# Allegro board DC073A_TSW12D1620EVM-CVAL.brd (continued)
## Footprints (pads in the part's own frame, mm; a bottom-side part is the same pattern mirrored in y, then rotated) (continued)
CQFP_HFG_36_0P635MM
  rect 1.778x0.229 smd: 1(-6.985,2.54) 2(-6.985,1.905) 3(-6.985,1.27) 4(-6.985,0.635) 5(-6.985,0) 6(-6.985,-0.635) 7(-6.985,-1.27) 8(-6.985,-1.905) 9(-6.985,-2.54) 19(6.985,-2.54) 20(6.985,-1.905) 21(6.985,-1.27) 22(6.985,-0.635) 23(6.985,0) 24(6.985,0.635) 25(6.985,1.27) 26(6.985,1.905) 27(6.985,2.54)
  rect 0.229x1.778 smd: 10(-2.54,-6.985) 11(-1.905,-6.985) 12(-1.27,-6.985) 13(-0.635,-6.985) 14(0,-6.985) 15(0.635,-6.985) 16(1.27,-6.985) 17(1.905,-6.985) 18(2.54,-6.985) 28(2.54,6.985) 29(1.905,6.985) 30(1.27,6.985) 31(0.635,6.985) 32(0,6.985) 33(-0.635,6.985) 34(-1.27,6.985) 35(-1.905,6.985) 36(-2.54,6.985)
  rect 6.502x6.502 smd: 37(0,0)
DBV5
  rect 1.4x0.5 smd: 1(-1.1,0.95) 2(-1.1,0) 3(-1.1,-0.95) 4(1.1,-0.95) 5(1.1,0.95)
DIODE_MBRB2515L
  rect 3.048x1.016 smd: 1(5.652,-2.54) 3(5.652,2.54)
  round 0.013 smd: 2(5.652,0)
  rect 8.382x10.668 smd: 4(-5.652,0)
DIODE_SM_1N4148W
  rect 0.889x0.94 smd: 1(-1.575,0) 2(1.575,0)
DUAL_FLATPACK_TPS7H1101-SP
  rect 1.422x0.551 smd: 1(-7.303,4.445) 2(-7.303,3.175) 3(-7.303,1.905) 4(-7.303,0.635) 5(-7.303,-0.635) 6(-7.303,-1.905) 7(-7.303,-3.175) 8(-7.303,-4.445) 9(7.303,-4.445) 10(7.303,-3.175) 11(7.303,-1.905) 12(7.303,-0.635) 13(7.303,0.635) 14(7.303,1.905) 15(7.303,3.175) 16(7.303,4.445)
  rect 6.223x8.89 smd: 17(0,0)
HDR_THVT_1X2_100_M
  rect 1.473x1.473 hole 0.965: 1(0,0)
  round 1.473 hole 0.965: 2(0,-2.54)
HDR_THVT_1X3_100_M
  rect 1.575x1.575 hole 1.016: 1(0,0)
  round 1.575 hole 1.016: 2(0,-2.54) 3(0,-5.08)
HDR_THVT_1X4_100_M
  rect 1.473x1.473 hole 0.965: 1(0,0)
  round 1.473 hole 0.965: 2(0,-2.54) 3(0,-5.08) 4(0,-7.62)
IND_0402
  rect 0.406x0.66 smd: 1(-0.432,0) 2(0.432,0)
IND_0603
  rect 0.635x1.016 smd: 1(-0.635,0) 2(0.635,0)
IND_SM_6P7MMX6P7MM
  rect 2.5x2.4 smd: 1(-3.1,0) 2(3.1,0)
LCCC_14_5P5X6MM_1P27
  custom 0.159x0.159 smd: 1(-2.642,1.27) 3(-2.642,-1.27) 4(-1.905,-2.413) 7(1.905,-2.413) 8(2.642,-1.27) 10(2.642,1.27) 11(1.905,2.388) 14(-1.905,2.388)
  rect 1.524x0.635 smd: 2(-2.642,0) 9(2.642,0)
  rect 0.635x1.524 smd: 5(-0.635,-2.413) 6(0.635,-2.413) 12(0.635,2.388) 13(-0.635,2.388)
  rect 2.997x2.489 smd: 15(0,0)
LED_0805
  rect 1.422x1.524 smd: 1(-1.143,0) 2(1.143,0)
LMT01-SP
  rect 0.533x4.445 smd: 1(-0.635,0) 2(0.635,0)
LQFP_64_402X402_20
  round 1.016 smd: (-6.35,6.35) (6.35,-6.35)
  rect 2.032x0.33 smd: 1(-5.625,3.75) 2(-5.625,3.25) 3(-5.625,2.75) 4(-5.625,2.25) 5(-5.625,1.75) 6(-5.625,1.25) 7(-5.625,0.75) 8(-5.625,0.25) 9(-5.625,-0.25) 10(-5.625,-0.75) 11(-5.625,-1.25) 12(-5.625,-1.75) 13(-5.625,-2.25) 14(-5.625,-2.75) 15(-5.625,-3.25) 16(-5.625,-3.75) 33(5.625,-3.75) 34(5.625,-3.25) 35(5.625,-2.75) 36(5.625,-2.25) 37(5.625,-1.75) 38(5.625,-1.25) 39(5.625,-0.75) 40(5.625,-0.25) 41(5.625,0.25) 42(5.625,0.75) 43(5.625,1.25) 44(5.625,1.75) 45(5.625,2.25) 46(5.625,2.75) 47(5.625,3.25) 48(5.625,3.75)
  rect 0.33x2.032 smd: 17(-3.75,-5.625) 18(-3.25,-5.625) 19(-2.75,-5.625) 20(-2.25,-5.625) 21(-1.75,-5.625) 22(-1.25,-5.625) 23(-0.75,-5.625) 24(-0.25,-5.625) 25(0.25,-5.625) 26(0.75,-5.625) 27(1.25,-5.625) 28(1.75,-5.625) 29(2.25,-5.625) 30(2.75,-5.625) 31(3.25,-5.625) 32(3.75,-5.625) 49(3.75,5.625) 50(3.25,5.625) 51(2.75,5.625) 52(2.25,5.625) 53(1.75,5.625) 54(1.25,5.625) 55(0.75,5.625) 56(0.25,5.625) 57(-0.25,5.625) 58(-0.75,5.625) 59(-1.25,5.625) 60(-1.75,5.625) 61(-2.25,5.625) 62(-2.75,5.625) 63(-3.25,5.625) 64(-3.75,5.625)
MFG125_PLATED
  round 3.556 hole 3.175: 1(0,0)
MSOP_8_118X118_0P65MM
  rect 1.45x0.46 smd: 1(-2.2,0.975) 2(-2.2,0.325) 3(-2.2,-0.325) 4(-2.2,-0.975) 5(2.2,-0.975) 6(2.2,-0.325) 7(2.2,0.325) 8(2.2,0.975)
OSC_6_SM_SIA0006B
  rect 0.914x0.635 smd: 1(-1.05,1.27) 2(-1.05,0) 3(-1.05,-1.27) 4(1.05,-1.27) 5(1.05,0) 6(1.05,1.27)
PROBE_POINT_30PAD
  round 0.762 smd: 1(0,0)
QFN_48_281X281_0P50MM_RGZ
  oval 0.838x0.279 smd: 1(-3.525,2.75) 2(-3.525,2.25) 3(-3.525,1.75) 4(-3.525,1.25) 5(-3.525,0.75) 6(-3.525,0.25) 7(-3.525,-0.25) 8(-3.525,-0.75) 9(-3.525,-1.25) 10(-3.525,-1.75) 11(-3.525,-2.25) 12(-3.525,-2.75) 25(3.525,-2.75) 26(3.525,-2.25) 27(3.525,-1.75) 28(3.525,-1.25) 29(3.525,-0.75) 30(3.525,-0.25) 31(3.525,0.25) 32(3.525,0.75) 33(3.525,1.25) 34(3.525,1.75) 35(3.525,2.25) 36(3.525,2.75)
  oval 0.279x0.838 smd: 13(-2.75,-3.525) 14(-2.25,-3.525) 15(-1.75,-3.525) 16(-1.25,-3.525) 17(-0.75,-3.525) 18(-0.25,-3.525) 19(0.25,-3.525) 20(0.75,-3.525) 21(1.25,-3.525) 22(1.75,-3.525) 23(2.25,-3.525) 24(2.75,-3.525) 37(2.75,3.525) 38(2.25,3.525) 39(1.75,3.525) 40(1.25,3.525) 41(0.75,3.525) 42(0.25,3.525) 43(-0.25,3.525) 44(-0.75,3.525) 45(-1.25,3.525) 46(-1.75,3.525) 47(-2.25,3.525) 48(-2.75,3.525)
  rect 5.6x5.6 smd: 49(0,0)
SMA_THVT_SMT_250X250
  round 0.787 smd: 1(0,0)
  round 1.829 hole 1.499: 2(-2.54,-2.54) 3(2.54,-2.54) 4(2.54,2.54) 5(-2.54,2.54)
SO_8_207X207_50
  rect 1.702x0.66 smd: 1(-3.645,1.905) 2(-3.645,0.635) 3(-3.645,-0.635) 4(-3.645,-1.905) 5(3.645,-1.905) 6(3.645,-0.635) 7(3.645,0.635) 8(3.645,1.905)
SOIC_8_197X157_50
  rect 2.159x0.61 smd: 1(-2.44,1.905) 2(-2.44,0.635) 3(-2.44,-0.635) 4(-2.44,-1.905) 5(2.44,-1.905) 6(2.44,-0.635) 7(2.44,0.635) 8(2.44,1.905)
SON_Q5B_8
  rect 1.372x0.711 smd: 1(-2.767,1.905) 2(-2.767,0.635) 3(-2.767,-0.635) 4(-2.767,-1.905) 5(2.767,-1.905) 6(2.767,-0.635) 7(2.767,0.635) 8(2.767,1.905)
SOT_5_120X69_37
  rect 0.61x1.524 smd: 1(-0.95,-1.75) 2(0,-1.75) 3(0.95,-1.75) 4(0.95,1.75) 5(-0.95,1.75)
SOT_5_120X69_57
  rect 0.61x1.524 smd: 1(-0.95,-1.75) 2(0,-1.75) 3(0.95,-1.75) 4(0.95,1.75) 5(-0.95,1.75)
SW_SMVT_SPST_ES02
  rect 0.889x2.159 smd: 1(-2.54,-4.445) 2(0,-4.445) 3(2.54,-4.445)
  rect 2.413x1.524 smd: 4(-5.385,4.445) 5(5.385,4.445)
SW_THVT_SPST_PTS635SL43
  round 2.159 hole 1.397: 1(-3.251,0) 2(3.251,0)
TANT_B
  rect 2.032x2.286 smd: 1(-1.524,0) 2(1.524,0)
TANT_D
  rect 2.108x2.591 smd: 1(-2.896,0) 2(2.896,0)
TANT_X
  rect 2.108x2.591 smd: 1(-2.896,0) 2(2.896,0)
TFMR_5_150X150_50
  rect 1.651x0.762 smd: 1(1.587,1.27) 2(1.587,0) 3(1.587,-1.27) 4(-1.587,-1.27) 6(-1.587,1.27)
TP_THVT_100_RND
  round 2.54 hole 1.016: 1(0,0)
TP_THVT_125_RND_063D
  round 2.362 hole 1.6: 1(0,0)
TSSOP_16_201X177_26
  rect 1.778x0.406 smd: 1(-2.825,2.275) 2(-2.825,1.625) 3(-2.825,0.975) 4(-2.825,0.325) 5(-2.825,-0.325) 6(-2.825,-0.975) 7(-2.825,-1.625) 8(-2.825,-2.275) 9(2.825,-2.275) 10(2.825,-1.625) 11(2.825,-0.975) 12(2.825,-0.325) 13(2.825,0.325) 14(2.825,0.975) 15(2.825,1.625) 16(2.825,2.275)
unnamed#2
  round 1.016 smd: 1(0,0)
XTAL_2_SM_126X197
  rect 1.9x2.4 smd: 1(-2.05,0) 2(2.05,0)
XTAL_2_SM_MS3V-T1R_264X55
  rect 2.413x1.524 smd: (-3.1,0)
  rect 1.118x0.61 smd: 1(2.45,-0.45) 2(2.45,0.45)
XTAL_HC-49UX
  round 1.524 hole 0.914: 1(0,0) 2(5.08,0)

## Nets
1V9A: C78.1 C79.1 C80.1 C81.1 C82.1 C83.1 C84.1 C85.1 C86.1 C87.1 C88.1 C89.1 C90.1 C91.1 C92.1 C93.1 C94.1 C95.1 C96.1 R85.2 U4.A2(VA#A2) U4.A6(VA#A6) U4.B6(VA#B6) U4.C7(VA#C7) U4.D1(VA#D1) U4.D8(VA#D8) U4.D9(VA#D9) U4.E1(VA#E1) U4.F1(VA#F1) U4.H4(VA#H4) U4.N4(VA#N4) U4.R1(VA#R1) U4.T1(VA#T1) U4.U8(VA#U8) U4.U9(VA#U9) U4.W6(VA#W6) U4.Y2(VA#Y2) U4.Y6(VA#Y6)
1V9DR: C97.1 C98.1 C99.1 C100.1 C101.1 C102.1 C103.1 C104.1 C105.1 C106.1 C107.1 C108.1 C109.1 C110.1 C111.1 C112.1 C113.1 R87.2 U4.A11(VDR#A11) U4.A15(VDR#A15) U4.C18(VDR#C18) U4.D11(VDR#D11) U4.D15(VDR#D15) U4.D17(VDR#D17) U4.J17(VDR#J17) U4.J20(VDR#J20) U4.R17(VDR#R17) U4.R20(VDR#R20) U4.T17(VDR#T17) U4.U11(VDR#U11) U4.U15(VDR#U15) U4.U16(VDR#U16) U4.Y11(VDR#Y11) U4.Y15(VDR#Y15)
1V9E: C117.1 C118.1 C119.1 C120.1 C121.1 C122.1 C123.1 R86.2 U4.A8(VE#A8) U4.B9(VE#B9) U4.C8(VE#C8) U4.V8(VE#V8) U4.W9(VE#W9) U4.Y8(VE#Y8)
1V9TC: C63.1 C64.1 C65.1 C66.1 C67.1 C68.1 C69.1 C70.1 C71.1 C72.1 C73.1 C74.1 C75.1 C76.1 C77.1 R88.2 U4.G1(VTC#G1) U4.G3(VTC#G3) U4.G4(VTC#G4) U4.H2(VTC#H2) U4.J3(VTC#J3) U4.K3(VTC#K3) U4.L3(VTC#L3) U4.M3(VTC#M3) U4.N2(VTC#N2) U4.P1(VTC#P1) U4.P3(VTC#P3) U4.P4(VTC#P4) U4.R3(VTC#R3) U4.R4(VTC#R4)
3.3VLMX: C215.1 C216.1 C217.1 FB7.1 FB8.1 FB9.1 R180.1 U18.6(OUT1) U18.7(OUT2) U18.8(OUT3)
4.8VLMH: C226.1 C227.1 C228.1 FB10.1 R182.1 U19.6(OUT1) U19.7(OUT2) U19.8(OUT3)
5.0V_IN: J33.1 SW3.1
5VIN: C180.1 C181.1 C182.1 C183.1 C206.1 C207.1 C213.1 C214.1 C224.1 C225.1 F1.2 Q1.1(S1) Q1.2(S2) Q1.3(S3) R160.1 R161.1 R162.1 R178.1 U15.5(VIN) U15.6(PVIN#6) U15.7(PVIN#7) U17.15(VIN) U18.1(\\S\H\D\N\) U18.2(IN1) U18.3(IN2) U18.4(IN3) U19.1(\\S\H\D\N\) U19.2(IN1) U19.3(IN2) U19.4(IN3)
+2.2V: C185.1 C186.1 C187.1 C188.1 C194.1 C195.1 C196.1 L11.2 PP10.1 R163.2 R168.1 R170.1
+2.5V: C44.1 C45.1 C46.2 C47.2 C48.2 C49.2 C50.2 C51.2 C52.2 C55.2 C56.2 C208.1 C209.1 FB6.2 JP10.1(PIN1) PP18.1 U6.1(VCC#1) U6.9(VCC#9) U6.10(VCC#10) U6.17(VCC#17) U6.18(VCC#18) U6.27(VCC#27) U6.28(VCC#28) U6.35(VCC#35) U6.36(VCC#36)
+3.3V_LMX: C127.1 C129.2 C133.2 C218.1 C219.1 C220.1 C221.1 FB8.2 PP15.1 R98.1 R101.1 R103.1 R106.1 R108.1 R109.1 R110.1 Y1.6(VDD)
+3.3V_LMXRF: C222.1 C223.1 FB9.2 L9.2 L10.2 PP16.1
+4.8V_LMH: C9.1 C10.1 C11.1 C12.1 C25.1 C26.1 C27.1 C28.1 C229.1 C230.1 FB10.2 JP1.1 JP2.1 PP17.1 R14.1 U1.1(VS+#1) U1.10(VS+#10) U2.1(VS+#1) U2.10(VS+#10)
GND: C4.2 C7.1 C9.2 C10.2 C11.2 C12.2 C15.2 C19.2 C21.1 C25.2 C26.2 C27.2 C28.2 C30.2 C31.2 C34.2 C35.2 C36.2 C38.1 C39.1 C44.2 C45.2 C46.1 C47.1 C48.1 C49.1 C50.1 C51.1 C52.1 C55.1 C56.1 C63.2 C64.2 C65.2 C66.2 C67.2 C68.2 C69.2 C70.2 C71.2 C72.2 C73.2 C74.2 C75.2 C76.2 C77.2 C78.2 C79.2 C80.2 C81.2 C82.2 C83.2 C84.2 C85.2 C86.2 C87.2 C88.2 C89.2 C90.2 C91.2 C92.2 C93.2 C94.2 C95.2 C96.2 C97.2 C98.2 C99.2 C100.2 C101.2 C102.2 C103.2 C104.2 C105.2 C106.2 C107.2 C108.2 C109.2 C110.2 C111.2 C112.2 C113.2 C114.2 C115.2 C116.2 C117.2 C118.2 C119.2 C120.2 C121.2 C122.2 C123.2 C124.2 C125.2 C126.2 C127.2 C129.1 C130.2 C132.2 C133.1 C134.2 C137.2 C139.2 C141.2 C142.2 C143.2 C145.2 C146.2 C147.1 C148.1 C149.2 C150.2 C151.1 C152.1 C153.1 C154.1 C155.1 C156.2 C157.2 C158.2 C159.2 C160.2 C161.2 C162.2 C163.2 C164.2 C165.2 C166.2 C167.2 C168.2 C169.2 C170.2 C171.2 C172.2 C173.2 C174.2 C175.2 C176.2 C177.2 C178.2 C179.2 C180.2 C181.2 C182.2 C183.2 C184.2 C185.2 C186.2 C187.2 C189.2 C190.2 C191.2 C192.2 C193.2 C194.2 C195.2 C196.2 C198.2 C199.2 C200.2 C201.2 C202.2 C203.2 C204.2 C205.2 C206.2 C207.2 C208.2 C209.2 C210.2 C211.2 C212.2 C213.2 C214.2 C216.2 C217.2 C218.2 C219.2 C220.2 C221.2 C222.2 C223.2 C224.2 C225.2 C227.2 C228.2 C229.2 C230.2 C236.2 C237.2 C238.2 D6.2(CATHODE) D8.2(CATHODE) D9.1 D9.3 D10.2(CATHODE) FB4.2 FB5.2 J1.2(SHIELD1) J1.3(SHIELD2) J1.4(SHIELD3) J1.5(SHIELD4) J2.2(SHIELD1) J2.3(SHIELD2) J2.4(SHIELD3) J2.5(SHIELD4) J3.2(SHIELD1) J3.3(SHIELD2) J3.4(SHIELD3) J3.5(SHIELD4) J4.2(SHIELD1) J4.3(SHIELD2) J4.4(SHIELD3) J4.5(SHIELD4) J5.2(SHIELD1) J5.3(SHIELD2) J5.4(SHIELD3) J5.5(SHIELD4) J6.2(SHIELD1) J6.3(SHIELD2) J6.4(SHIELD3) J6.5(SHIELD4) J10.1 J13.2(SHIELD1) J13.3(SHIELD2) J13.4(SHIELD3) J13.5(SHIELD4) J14.2(SHIELD1) J14.3(SHIELD2) J14.4(SHIELD3) J14.5(SHIELD4) J15.2(SHIELD1) J15.3(SHIELD2) J15.4(SHIELD3) J15.5(SHIELD4) J16.2(SHIELD1) J16.3(SHIELD2) J16.4(SHIELD3) J16.5(SHIELD4) J17.2(SHIELD1) J17.3(SHIELD2) J17.4(SHIELD3) J17.5(SHIELD4) J18.2(SHIELD1) J18.3(SHIELD2) J18.4(SHIELD3) J18.5(SHIELD4) J19.2(SHIELD1) J19.3(SHIELD2) J19.4(SHIELD3) J19.5(SHIELD4) J20.2(SHIELD1) J20.3(SHIELD2) J20.4(SHIELD3) J20.5(SHIELD4) J21.2(SHIELD1) J21.3(SHIELD2) J21.4(SHIELD3) J21.5(SHIELD4) J22.2(SHIELD1) J22.3(SHIELD2) J22.4(SHIELD3) J22.5(SHIELD4) J24.2 J26.2(SHIELD1) J26.3(SHIELD2) J26.4(SHIELD3) J26.5(SHIELD4) J27.2(SHIELD1) J27.3(SHIELD2) J27.4(SHIELD3) J27.5(SHIELD4) J28.A1 J28.A4 J28.A5 J28.A8 J28.A9 J28.A12 J28.A13 J28.A16 J28.A17 J28.A20 J28.A21 J28.A24 J28.A25 J28.A28 J28.A29 J28.A32 J28.A33 J28.A36 J28.A37 J28.A40 J28.B2 J28.B3 J28.B6 J28.B7 J28.B10 J28.B11 J28.B14 J28.B15 J28.B18 J28.B19 J28.B22 J28.B23 J28.B26 J28.B27 J28.B30 J28.B31 J28.B34 J28.B35 J28.B38 J28.B39 J28.C1 J28.C4 J28.C5 J28.C8 J28.C9 J28.C12 J28.C13 J28.C16 J28.C17 J28.C21 J28.C24 J28.C25 J28.C28 J28.C29 J28.C32 J28.C33 J28.C36 J28.C38 J28.C40 J28.D2 J28.D3 J28.D6 J28.D7 J28.D10 J28.D13 J28.D16 J28.D22 J28.D25 J28.D28 J28.D37 J28.D39 J28.E1 J28.E4 J28.E5 J28.E11 J28.E17 J28.E20 J28.E23 J28.E26 J28.E29 J28.E32 J28.E35 J28.E38 J28.E40 J28.F2 J28.F3 J28.F9 J28.F12 J28.F15 J28.F18 J28.F21 J28.F24 J28.F27 J28.F30 J28.F33 J28.F36 J28.F39 J28.G1 J28.G4 J28.G5 J28.G8 J28.G11 J28.G14 J28.G20 J28.G23 J28.G26 J28.G29 J28.G32 J28.G35 J28.G38 J28.G40 J28.H3 J28.H9 J28.H12 J28.H21 J28.H24 J28.H27 J28.H30 J28.H33 J28.H36 J28.H39 J28.J1 J28.J5 J28.J8 J28.J11 J28.J14 J28.J20 J28.J26 J28.J29 J28.J32 J28.J35 J28.J38 J28.J40 J28.K3 J28.K6 J28.K9 J28.K15 J28.K18 J28.K21 J28.K24 J28.K27 J28.K30 J28.K33 J28.K36 J28.K39 J30.3 J32.5(GND) J32.6(GND1) J32.7(GND2) J32.8(GND3) J32.9(GND4) J33.2 J33.3 J34.2 J36.9 JP3.3(PIN3) JP4.3(PIN3) JP5.3(PIN3) JP6.3(PIN3) JP7.3(PIN3) JP8.3(PIN3) JP9.3(PIN3) MT1.1 MT2.1 MT3.1 MT4.1 R5.2 R8.2 R10.2 R13.2 R15.2 R20.2 R21.2 R26.2 R28.2 R32.2 R33.2 R34.2 R37.2 R38.2 R51.2 R61.2 R62.2 R67.2 R68.2 R71.2 R72.2 R77.2 R78.2 R84.2 R91.2 R92.1 R94.1 R95.2 R96.2 R102.2 R111.2 R113.2 R118.2 R127.2 R140.1 R164.1 R165.1 R167.2 R175.2 R176.2 R179.2 R181.2 R183.2 R186.1 R189.2 SW1.1 SW2.1 T1.4(PRIMARY) TP11.1(TP) TP12.1(TP) TP13.1(TP) TP14.1(TP) TP15.1(TP) U1.3(VS-#3) U1.8(VS-#8) U1.11(GND#11) U1.14(GND#14) U1.15(PWRPAD) U2.3(VS-#3) U2.8(VS-#8) U2.11(GND#11) U2.14(GND#14) U2.15(PWRPAD) U3.4(V-) U4.A1(GND#A1) U4.A7(GND#A7) U4.A9(GNDE#A9) U4.A13(GNDDR#A13) U4.A17(GNDDR#A17) U4.A20(GNDDR#A20) U4.AA2(GND#AA2) U4.AA3(GND#AA3) U4.AA4(GND#AA4) U4.AA5(GND#AA5) U4.AA6(GND#AA6) U4.AA7(GND#AA7) U4.AA8(GND#AA8) U4.AA9(GND#AA9) U4.AA10(GND#AA10) U4.AA11(GND#AA11) U4.AB1(GND#AB1) U4.AB2(GND#AB2) U4.AB3(GND#AB3) U4.AB4(GND#AB4) U4.AB5(GND#AB5) U4.AB6(GND#AB6) U4.AB7(GND#AB7) U4.AB8(GND#AB8) U4.AB9(GND#AB9) U4.AB10(GND#AB10) U4.AB11(GND#AB11) U4.AC1(GND#AC1) U4.AC2(GND#AC2) U4.AC3(GND#AC3) U4.AC4(GND#AC4) U4.AC5(GND#AC5) U4.AC6(GND#AC6) U4.AC7(GND#AC7) U4.AC8(GND#AC8) U4.AC9(GND#AC9) U4.AC10(GND#AC10) U4.AC11(GND#AC11) U4.AD1(GND#AD1) U4.AD2(GND#AD2) U4.AD3(GND#AD3) U4.AD4(GND#AD4) U4.AD5(GND#AD5) U4.AD6(GND#AD6) U4.AD7(GND#AD7) U4.AD8(GND#AD8) U4.AD9(GND#AD9) U4.AD10(GND#AD10) U4.AD11(GND#AD11) U4.AE1(GND#AE1) U4.AE2(GND#AE2) U4.AE3(GND#AE3) U4.AE4(GND#AE4) U4.AE5(GND#AE5) U4.AE6(GND#AE6) U4.AE7(GND#AE7) U4.AE8(GND#AE8) U4.AE9(GND#AE9) U4.AE10(GND#AE10) U4.AE11(GND#AE11) U4.AF1(GND#AF1) U4.AF2(GND#AF2) U4.AF3(GND#AF3) U4.AF4(GND#AF4) U4.AF5(GND#AF5) U4.AF6(GND#AF6) U4.AF7(GND#AF7) U4.AF8(GND#AF8) U4.AF9(GND#AF9) U4.AF10(GND#AF10) U4.AF11(GND#AF11) U4.AG1(GND#AG1) U4.AG2(GND#AG2) U4.AG3(GND#AG3) U4.AG4(GND#AG4) U4.AG5(GND#AG5) U4.AG6(GND#AG6) U4.AG7(GND#AG7) U4.AG8(GND#AG8) U4.AG9(GND#AG9) U4.AG10(GND#AG10) U4.AG11(GND#AG11) U4.AH1(GND#AH1) U4.AH2(GND#AH2) U4.AH3(GND#AH3) U4.AH4(GND#AH4) U4.AH5(GND#AH5) U4.AH6(GND#AH6) U4.AH7(GND#AH7) U4.AH8(GND#AH8) U4.AH9(GND#AH9) U4.AH10(GND#AH10) U4.AH11(GND#AH11) U4.AJ1(GND#AJ1) U4.AJ2(GND#AJ2) U4.AJ3(GND#AJ3) U4.AJ4(GND#AJ4) U4.AJ5(GND#AJ5) U4.AJ6(GND#AJ6) U4.AJ7(GND#AJ7) U4.AJ8(GND#AJ8) U4.AJ9(GND#AJ9) U4.AJ10(GND#AJ10) U4.AJ11(GND#AJ11) U4.AK1(GND#AK1) U4.AK2(GND#AK2) U4.AK3(GND#AK3) U4.AK4(GND#AK4) U4.AK5(GND#AK5) U4.AK6(GND#AK6) U4.AK7(GND#AK7) U4.AK8(GND#AK8) U4.AK9(GND#AK9) U4.AK10(GND#AK10) U4.AK11(GND#AK11) U4.AL1(GND#AL1) U4.AL2(GND#AL2) U4.AL3(GND#AL3) U4.AL4(GND#AL4) U4.AL5(GND#AL5) U4.AL6(GND#AL6) U4.AL7(GND#AL7) U4.AL8(GND#AL8) U4.AL9(GND#AL9) U4.AL10(GND#AL10) U4.AL11(GND#AL11) U4.B2(GND#B2) U4.B7(GND#B7) U4.B8(GNDE#B8) U4.C6(GND#C6) U4.C9(GNDE#C9) U4.D4(GND#D4) U4.D5(GND#D5) U4.D13(GNDDR#D13) U4.D16(GNDDR#D16) U4.E4(GND#E4) U4.E17(GNDDR#E17) U4.F2(GNDTC#F2) U4.F17(GNDDR#F17) U4.F20(GNDDR#F20) U4.G2(GNDTC#G2) U4.H3(GNDTC#H3) U4.J2(GNDTC#J2) U4.K1(GND#K1) U4.K4(GNDTC#K4) U4.L1(GND#L1) U4.L4(GNDTC#L4) U4.M2(GNDTC#M2) U4.M17(GNDDR#M17) U4.M20(GNDDR#M20) U4.N3(GNDTC#N3) U4.P2(GNDTC#P2) U4.R2(GNDTC#R2) U4.T2(GNDTC#T2) U4.T3(GNDTC#T3) U4.T4(GND#T4) U4.U1(GNDTC#U1) U4.U4(GND#U4) U4.U5(GND#U5) U4.U13(GNDDR#U13) U4.U17(GNDDR#U17) U4.V9(GNDE#V9) U4.V18(GNDDR#V18) U4.W2(GND#W2) U4.W7(GND#W7) U4.W8(GNDE#W8) U4.Y1(GND#Y1) U4.Y7(GND#Y7) U4.Y9(GNDE#Y9) U4.Y13(GNDDR#Y13) U4.Y17(GNDDR#Y17) U4.Y20(GNDDR#Y20) U5.5(A0) U5.6(GND) U5.11(PAD) U6.37(THERMPAD) U7.3(FS0) U7.4(FS1) U7.6(GND#6) U7.8(GND#8) U7.10(GND#10) U7.15(FS2) U7.16(FS3) U7.17(FS4) U7.18(FS5) U7.19(FS6) U7.20(FS7) U7.23(GND#23) U7.24(GND#24) U7.28(GND#28) U7.31(GND#31) U7.35(GND#35) U7.38(GND#38) U7.40(GND#40) U7.43(SYSREFREG) U7.51(GND#51) U7.54(GND#54) U7.60(GND#60) U7.61(GND#61) U7.65(PWRPAD) U8.3(A2) U8.4(VSS) U9.7(DIR3) U9.10(GND) U10.2(GND) U11.3(GND) U12.1(GND#1) U12.5(GND#5) U12.10(AGND) U12.11(GND#11) U12.13(TEST) U12.15(GND#15) U12.25(GND#25) U12.35(GND#35) U12.47(GND#47) U12.51(GND#51) U13.5(VSS) U14.2(GND) U15.1(GND) U15.8(PGND#8) U15.9(PGND#9) U15.10(PGND#10) U15.21(PWRPAD) U16.8(GND) U16.17(PWRPAD) U17.1(GND#1) U17.8(GND#8) U17.9(GND#9) U17.11(COMP IN) U17.16(GND#16) U18.10(GND) U18.11(PWRPAD) U19.10(GND) U19.11(PWRPAD) U20.36(DVSS) U20.49(THERMPAD) Y1.3(GND)
VBUS: C167.1 R132.1 U10.1(IN) U10.3(EN)
VBUSS: C163.1 FB3.1 U10.5(OUT)
VDDD33: C30.1 C31.1 C34.1 C35.1 C36.1 C156.1 C166.1 C170.1 C176.1 C177.1 C178.1 C179.1 C211.1 C212.1 C236.1 C237.1 D5.1(ANODE) D7.1(ANODE) FB1.1 FB2.1 FB7.2 J36.4 JP11.1(PIN1) JP12.3(PIN3) JP13.3(PIN3) PP14.1 R39.1 R41.1 R47.1 R48.1 R141.1 R142.1 R145.1 R146.1 R147.1 R148.1 R187.1 R190.1 U3.8(V+) U5.1(V+) U5.10(A1) U9.1(DIR1) U9.2(DIR2) U9.8(DIR4) U9.16(VCCA) U11.5(VCC) U12.20(VCCIO#20) U12.31(VCCIO#31) U12.42(VCCIO#42) U12.56(VCCIO#56) U13.8(VCC) U20.37(DVCC)
VDDL19: C157.1 C192.1 C193.1 FB4.3 J12.1 JP3.1(PIN1) JP4.1(PIN1) JP5.1(PIN1) JP6.1(PIN1) JP7.1(PIN1) JP8.1(PIN1) JP9.1(PIN1) PP12.1 R29.1 R30.1 R35.1 R119.1 U9.15(VCCB)
VEE: JP10.3(PIN3) R84.1 U6.8(VEE)
VINI+: C2.2 R1.2 U4.H1(VINI+)
VINI-: C14.2 R12.2 U4.J1(VINI-)
VINQ+: C24.2 R27.2 U4.N1(VINQ+)
VINQ-: C17.2 R16.2 U4.M1(VINQ-)
1P8V_USB: C168.1 C169.1 C171.1 C172.1 C173.1 PP9.1 U12.12(VCORE#12) U12.37(VCORE#37) U12.49(VREGOUT) U12.64(VCORE#64)
2: D9.2
3P3USB: C160.1 C161.1 FB2.2 PP6.1 U12.9(VPLL)
3P3V_RX: PP3.1 R115.2
3P3VAUX: C155.2 J28.D32 J30.4 U8.8(VCC)
12P0V_RX: J28.C35 J28.C37
/CS: R191.2 U20.39(P2.3/TA0.0)
/RST: C238.1 J36.11 R190.2 SW2.2 U20.23(R\S\T\/NMI/SBWTDIO)
ADC_CLK: PP7.1 R122.2 U4.C5(SCLK)
ADC_SCSB: PP8.1 R125.2 U4.C4(\\S\C\S\)
ADC_SDI: PP4.1 R123.2 U4.B4(SDI)
ADC_SDO: PP5.1 R124.2 U4.A3(SDO)
AIN: C1.2 R3.1
AINI: C1.1 J2.1(CENTER) R5.1
AINQ: C29.1 J5.1(CENTER) R26.1
AIP: C6.2 R7.1
AQN: C16.2 R18.1
AQP: C29.2 R25.1
BDBUS0: R134.1 U12.26(BDBUS0)
BDBUS1: U11.2(A) U12.27(BDBUS1)
BDBUS2: R136.1 U12.28(BDBUS2)
BDBUS3: U11.1(O\E\) U12.29(BDBUS3)
CALRUN: R40.1 TP1.1(TP) U4.B5(CALRUN)
CALRUN_FMC: J28.G18 R40.2
CALTRG: J9.2 R38.1 U4.D6(CAL)
CDBUS0: R138.1 U12.38(CDBUS0)
CDBUS1: R143.1 U12.39(CDBUS1)
CDBUS2: R142.2 R149.1 U12.40(CDBUS2)
CDBUS3: R141.2 R150.1 U12.41(CDBUS3)
CDBUS4: R151.1 U12.43(CDBUS4)
CLK+: C40.1 R53.2 T1.3(SECONDARY)
CLK-: C43.1 R53.1 T1.1(SECONDARY_DOT)
CLKN: C42.2 C43.2 U4.V1(CLK-)
CLKP: C40.2 C41.2 U4.U2(CLK+)
CPOUT: C131.1 C132.1 R90.1 U7.22(CPOUT)
DCLK_DI+: C59.2 J28.D20 R195.2
DCLK_DI-: C60.2 J28.D21 R194.2
DCLK_DID+: C57.2 J28.G6
DCLK_DID-: C58.2 J28.G7
DCLK_DQ+: C61.2 J28.K25 R197.1
DCLK_DQ-: C62.2 J28.K26 R196.1
DCLK_DQD+: C53.2 J28.F4
DCLK_DQD-: C54.2 J28.F5
DCLK_RST+: J13.1(CENTER) U4.V2(DCLK_RST+)
DCLK_RST-: J16.1(CENTER) U4.W1(DCLK_RST-)
DCLKI+: R64.2 R73.2 U4.K19(DCLKI+)
DCLKI-: R65.2 R75.2 U4.K20(DCLKI-)
DCLKIN: R65.1 R194.1
DCLKIP: R64.1 R195.1
DCLKQ+: R80.2 R82.2 U4.L19(DCLKQ+)
DCLKQ-: R81.2 R83.2 U4.L20(DCLKQ-)
DCLKQN: R81.1 R196.2
DCLKQP: R80.1 R197.2
DDRPH: JP9.2(PIN2) U4.W4(DDRPH)
DES: JP7.2(PIN2) U4.V5(DES)
DEVCLKIN: J21.1(CENTER) T1.6(PRIMARY_DOT)
DI0+: J28.C22 U4.B18(DI0)
DI0-: J28.C23 U4.C17(DI0-)
DI1+: J28.H22 U4.B19(DI1+)
DI1-: J28.H23 U4.B20(DI1-)
DI2+: J28.G21 U4.C19(DI2+)
DI2-: J28.G22 U4.C20(DI2-)
DI3+: J28.H25 U4.D18(DI3+)
DI3-: J28.H26 U4.E18(DI3-)
DI4+: J28.G24 U4.D19(DI4+)
DI4-: J28.G25 U4.D20(DI4-)
DI5+: J28.D23 U4.E19(DI5+)
DI5-: J28.D24 U4.E20(DI5-)
DI6+: J28.H28 U4.F18(DI6+)
DI6-: J28.H29 U4.F19(DI6-)
DI7+: J28.G27 U4.G17(DI7+)
DI7-: J28.G28 U4.G18(DI7-)
DI8+: J28.D26 U4.G19(DI8+)
DI8-: J28.D27 U4.G20(DI8-)
DI9+: J28.C26 U4.H17(DI9+)
DI9-: J28.C27 U4.H18(DI9-)
DI10+: J28.H31 U4.H19(DI10+)
DI10-: J28.H32 U4.H20(DI10-)
DI11+: J28.G30 U4.J18(DI11+)
DI11-: J28.G31 U4.J19(DI11-)
DID0+: J28.D8 U4.A10(DID0+)
DID0-: J28.D9 U4.B10(DID0-)
DID1+: J28.H7 U4.C10(DID1+)
DID1-: J28.H8 U4.D10(DID1-)
DID2+: J28.G9 U4.B11(DID2+)
DID2-: J28.G10 U4.C11(DID2-)
DID3+: J28.H10 U4.A12(DID3+)
DID3-: J28.H11 U4.B12(DID3-)
DID4+: J28.D11 U4.C12(DID4+)
DID4-: J28.D12 U4.D12(DID4-)
DID5+: J28.C10 U4.B13(DID5+)
DID5-: J28.C11 U4.C13(DID5-)
DID6+: J28.H13 U4.A14(DID6+)
DID6-: J28.H14 U4.B14(DID6-)
DID7+: J28.G12 U4.C14(DID7+)
DID7-: J28.G13 U4.D14(DID7-)
DID8+: J28.D14 U4.B15(DID8+)
DID8-: J28.D15 U4.C15(DID8-)
DID9+: J28.C14 U4.A16(DID9+)
DID9-: J28.C15 U4.B16(DID9-)
DID10+: J28.H16 U4.B17(DID10+)
DID10-: J28.H17 U4.C16(DID10-)
DID11+: J28.G15 U4.A18(DID11+)
DID11-: J28.G16 U4.A19(DID11-)
DQ0+: J28.J24 U4.W18(DQ0+)
DQ0-: J28.J25 U4.V17(DQ0-)
DQ1+: J28.F22 U4.W19(DQ1+)
DQ1-: J28.F23 U4.W20(DQ1-)
DQ2+: J28.E21 U4.V19(DQ2+)
DQ2-: J28.E22 U4.V20(DQ2-)
DQ3+: J28.F25 U4.U18(DQ3+)
DQ3-: J28.F26 U4.T18(DQ3-)
DQ4+: J28.E24 U4.U19(DQ4+)
DQ4-: J28.E25 U4.U20(DQ4-)
DQ5+: J28.K28 U4.T19(DQ5+)
DQ5-: J28.K29 U4.T20(DQ5-)
DQ6+: J28.J27 U4.R18(DQ6+)
DQ6-: J28.J28 U4.R19(DQ6-)
DQ7+: J28.F28 U4.P17(DQ7+)
DQ7-: J28.F29 U4.P18(DQ7-)
DQ8+: J28.E27 U4.P19(DQ8+)
DQ8-: J28.E28 U4.P20(DQ8-)
DQ9+: J28.K31 U4.N17(DQ9+)
DQ9-: J28.K32 U4.N18(DQ9-)
DQ10+: J28.J30 U4.N19(DQ10+)
DQ10-: J28.J31 U4.N20(DQ10-)
DQ11+: J28.F31 U4.M18(DQ11+)
DQ11-: J28.F32 U4.M19(DQ11-)
DQD0+: J28.E2 U4.Y10(DQD0+)
DQD0-: J28.E3 U4.W10(DQD0-)
DQD1+: J28.K7 U4.V10(DQD1+)
DQD1-: J28.K8 U4.U10(DQD1-)
DQD2+: J28.J6 U4.W11(DQD2+)
DQD2-: J28.J7 U4.V11(DQD2-)
DQD3+: J28.F7 U4.Y12(DQD3+)
DQD3-: J28.F8 U4.W12(DQD3-)
DQD4+: J28.E6 U4.V12(DQD4+)
DQD4-: J28.E7 U4.U12(DQD4-)
DQD5+: J28.K10 U4.W13(DQD5+)
DQD5-: J28.K11 U4.V13(DQD5-)
DQD6+: J28.J9 U4.Y14(DQD6+)
DQD6-: J28.J10 U4.W14(DQD6-)
DQD7+: J28.F10 U4.V14(DQD7+)
DQD7-: J28.F11 U4.U14(DQD7-)
DQD8+: J28.E9 U4.W15(DQD8+)
DQD8-: J28.E10 U4.V15(DQD8-)
DQD9+: J28.K13 U4.Y16(DQD9+)
DQD9-: J28.K14 U4.W16(DQD9-)
DQD10+: J28.J12 U4.W17(DQD10+)
DQD10-: J28.J13 U4.V16(DQD10-)
DQD11+: J28.F13 U4.Y18(DQD11+)
DQD11-: J28.F14 U4.Y19(DQD11-)
ECEN: JP8.2(PIN2) U4.B3(\\E\C\E\)
EE_ADDR0_RX: J28.C34 U8.1(A0)
EE_ADDR1_RX: J28.D35 U8.2(A1)
EECLK: R146.2 U12.62(EECLK) U13.2(CLK)
EECS: R147.2 U12.63(EECS) U13.1(CS)
EEDATA: R157.1 U12.61(EEDATA) U13.3(DI)
FB+: C3.1 R2.2 U1.4(FB+)
FB-: C13.1 R11.2 U1.7(FB-)
FBQ+: C18.1 R17.2 U2.4(FB+)
FBQ-: C23.1 R24.2 U2.7(FB-)
FMC_ADC_SCSB: J28.H38 R131.2
FMC_ADC_SDI: J28.G36 R129.2
FMC_DATA: J28.G37 R121.2 R144.2
FMC_LMX_CAL: J28.J15 R156.2
FMC_LMX_SCSB: J28.G33 R153.2
FMC_LMX_SDI: J28.G19 R159.2
FMC_SCL: J28.C30 J30.2 U8.6(SCL)
FMC_SCLK: J28.H37 R117.2 R139.2
FMC_SDA: J28.C31 J30.1 U8.5(SDA)
FSR: JP6.2(PIN2) U4.Y3(FSR)
FTDI_ADC_DATA: R120.1 U12.17(ADBUS1)
FTDI_ADC_SCLK: R116.1 U12.16(ADBUS0)
FTDI_ADC_SCSB: R130.1 U12.19(ADBUS3)
FTDI_ADC_SDI: R128.1 U12.18(ADBUS2)
IN+: C13.2 R6.1 R7.2 R11.1 U1.6(IN+)
IN-: C3.2 R2.1 R3.2 R6.2 U1.5(IN-)
INI_+: J1.1(CENTER) R1.1
INI_-: J3.1(CENTER) R12.1
INQ_+: J4.1(CENTER) R16.1
INQ_-: J6.1(CENTER) R27.1
IPD: JP1.2 R13.1 U1.9(PD)
LMX_CAL: R150.2 R156.1 U7.5(CAL)
LMX_CLKM: C41.1 C140.2
LMX_CLKP: C42.1 C136.2
LMX_CSB: R149.2 R153.1 TP8.1(TP) U7.39(CSB)
LMX_OSCN: C135.1 U7.13(OSCINM)
LMX_OSCP: C128.1 U7.12(OSCINP)
LMX_SCK: R138.2 R139.1 TP6.1(TP) U7.26(SCK)
LMX_SDI: R143.2 R144.1 TP7.1(TP) U7.27(SDI)
LMX_SDO: R105.2 R151.2 R159.1
LMX_SYNC: PP1.1 R102.1 U7.9(SYNC)
LSPSM: JP3.2(PIN2) U4.V4(LSPSM)
MISO: R155.2 U20.21(P2.6/TB0.1)
MOSI: R192.2 U20.20(P2.5/TB0.0)
MUX_OUT: R105.1 R107.1 TP9.1(TP) U7.32(MUXOUT)
NDM: JP5.2(PIN2) U4.A5(NDM)
ORI+: J28.H34
ORI-: J28.H35
ORQ+: J28.E30
ORQ-: J28.E31
OSCI: C174.1 U12.2(OSCI) Y2.2
OSCO: C175.1 U12.3(OSCO) Y2.1
OUT+: R4.1 U1.13(OUT+)
OUT-: R9.1 U1.12(OUT-)
OUTQ+: R19.1 U2.13(OUT+)
OUTQ-: R23.1 U2.12(OUT-)
OVRI+: D2.1(ANODE) R56.2
OVRI-: C32.2 R31.1 R55.2 U3.2(INA-)
OVRQ+: D4.1(ANODE) R57.2
OVRQ-: C33.2 R36.1 R54.2 U3.6(INB-)
PDI: J7.2 R32.1 U4.U3(PDI)
PDQ: J8.2 R33.1 U4.V3(PDQ)
PG_RX1: J28.F1 J29.2 R112.2
PRSNT_M2C_L: J28.H2 R113.1
QN+: C23.2 R22.1 R24.1 R25.2 U2.6(IN+)
QN-: C18.2 R17.1 R18.2 R22.2 U2.5(IN-)
QPD: JP2.2 R28.1 U2.9(PD)
RCLK+: J14.1(CENTER) U4.Y4(RCLK+)
RCLK-: J17.1(CENTER) U4.W5(RCLK-)
RCOUT1+: J15.1(CENTER) U4.Y5(RCOUT1+)
RCOUT1-: J18.1(CENTER) U4.U6(RCOUT1-)
RCOUT2+: J19.1(CENTER) U4.V6(RCOUT2+)
RCOUT2-: J20.1(CENTER) U4.V7(RCOUT2-)
RECAL_EN: R110.2 R111.1 U7.45(RECAL_EN)
SCLK: R193.2 U20.40(P2.4/TA1.0)
TCK: J36.7 U20.15(PJ.3/TCK)
TCRIT1: R48.2 R49.2 TP4.1(TP) U5.4(\\T\H\E\R\M\)
TCRIT2: R47.2 TP3.1(TP) U5.7(\\A\L\E\R\T\/\T\H\E\R\M\2\)
TDI: J36.3 U20.13(PJ.1/TDI)
TDI_FMC: J28.D30 J31.1
TDIODE+: J11.1 R43.2 U4.E2(TDIODE+)
TDIODE-: J11.2 R45.2 U4.F3(TDIODE-)
TDIODEN: C37.2 R45.1 U5.3(D-)
TDIODEP: C37.1 R43.1 U5.2(D+)
TDO: J36.1 U20.12(PJ.0/TDO)
TDO_FMC: J28.D31 J31.2
TEST: J36.8 U20.22(TEST/SBWTCK)
TMP461_SMBCLK: R39.2 R134.2 U5.9(SCL)
TMP461_SMBDAT: R41.2 R133.2 R136.2 U5.8(SDA)
TMS: J36.5 U20.14(PJ.2/TMS/ACLK)
TPM: JP4.2(PIN2) R46.1 U4.A4(TPM)
TPM_FMC: J28.H19 R46.2
V_BUS: C164.1 C165.1 FB3.2 JP11.3(PIN3)
VA19: C200.1 C201.1 C202.1 C203.1 FB5.3 PP13.1 R85.1 R86.1 R87.1 R88.1
VADJ_RX: J28.E39 J28.F40 J28.G39 J28.H40 PP2.1 R112.1 R114.1
VBB: U6.5(VBB)
VBG: J12.2 TP2.1(TP) U4.B1(VBG)
VCM: C15.1 R14.2 R15.1 U1.2(CM) U2.2(CM)
VCMO: J10.2 U4.C2(VCMO)
VIO_B_M2C_RX: J28.J39 J28.K40 R114.2
VPHY: C158.1 C159.1 FB1.2 U12.4(VPHY)
VREGIN: C162.1 JP11.2(PIN2) U12.50(VREGIN)
VTUNE: C130.1 R89.2 U7.55(VTUNE)
N18123409: D9.4 F1.1 Q1.5(D5) Q1.6(D6) Q1.7(D7) Q1.8(D8) SW3.3 TP10.1(TP) U14.5(VIN)
N18340257: D8.1(ANODE) R160.2
N19955835: Q1.4(G) U14.4(GATE)
N20251064: C131.2 R95.1
N20251377: C134.1 R89.1 R90.2 TP5.1(TP)
N20258125: D6.1(ANODE) R107.2
N20447902: D5.2(CATHODE) R49.1
N20601243: D3.1(ANODE) U3.7(OUTB)
N20601382: D1.1(ANODE) U3.1(OUTA)
N20601403: D3.2(CATHODE) R37.1
N20601859: D1.2(CATHODE) R34.1
N20602433: C33.1 D4.2(CATHODE) R36.2 U3.5(INB+)
N20603216: C32.1 D2.2(CATHODE) R31.2 U3.3(INA+)
N20606076: J9.1 R35.2
N20760406: C215.2 R180.2 R181.1 U18.9(ADJ)
N20772111: C188.2 R163.1 R167.1 U15.17(VSENSE)
N20772147: C191.1 R166.2
N20772149: C190.1 R166.1 U15.18(COMP)
N20772252: R161.2 U15.20(PWRGD)
N20772286: R162.2 R164.2 U15.2(EN)
N20772300: R165.2 U15.3(RT)
N20772322: C189.1 U15.19(SS/TR)
N20772348: C184.1 U15.16(RECAP)
N20772352: L11.1 U15.11(PH1) U15.12(PH2) U15.13(PH3) U15.14(PH4) U15.15(PH5)
N20774965: R170.2 R174.1 U16.2(EN) U16.3(VIN#3) U16.4(VIN#4) U16.5(VIN#5) U16.6(VIN#6)
N20775006: C205.1 U16.1(SS)
N20775018: C197.1 U16.15(COMP)
N20775020: C197.2 C198.1 C199.1 R171.2 R172.1 R173.1 U16.11(VOUT#11) U16.12(VOUT#12) U16.13(VOUT#13) U16.14(VOUT#14)
N20775032: R171.1 U16.9(PWRGD)
N20775050: R175.1 U16.7(PCL)
N20775064: R174.2 U16.10(CS)
N20775144: C204.1 R173.2 R176.1 U16.16(FB)
N20776453: FB4.1 FB5.1 R169.1 R172.2
N20810898: PP11.1 U15.4(SYNC)
N21127493: R133.1 U11.4(Y)
N21129355: D7.2(CATHODE) R118.1
N21131028: R148.2 U12.14(RESETB)
N21131030: R140.2 U12.6(REF)
N21131895: R145.2 R157.2 U13.4(DO)
N21135480: J32.1(VBUS) R132.2
N21135675: J32.3(D+) R137.1
N21135677: J32.2(D-) R135.1
N21135903: R135.2 U12.7(DM)
N21135906: R137.2 U12.8(DP)
N21168383: C7.2 L3.1 R9.2
N21168467: C4.1 L1.1 R4.2
N21171643: C5.2 C8.1
N21171649: C5.1 L1.2 L2.1
N21171654: C8.2 L3.2 L4.1
N21171729: C2.1 L2.2
N21171732: C14.1 L4.2
N21175089: J7.1 R29.2
N21175349: J8.1 R30.2
N21187119: C126.1 U4.K2(VBIASI#K2)
N21187126: C125.1 U4.J4(VBIASI#J4)
N21187133: C124.1 U4.D7(VBIASI#D7)
N21188308: C116.1 U4.U7(VBIASQ#U7)
N21188315: C115.1 U4.M4(VBIASQ#M4)
N21188322: C114.1 U4.L2(VBIASQ#L2)
N21202974: R51.1 U4.W3(RSV)
N21203641: C39.2 U4.E3(RSV1)
N21203646: C38.2 U4.F4(RSV2)
N21203848: R42.2 U4.C3(REXT+)
N21203855: R42.1 U4.D3(REXT-)
N21203893: R44.2 U4.C1(RTRIM+)
N21203895: R44.1 U4.D2(RTRIM-)
N21228014: R56.1 U4.K17(ORI+)
N21228016: R55.1 U4.K18(ORI-)
N21228048: R57.1 U4.L17(ORQ+)
N21228050: R54.1 U4.L18(ORQ-)
N21241287: C6.1 R8.1 R10.1
N21267772: C21.2 L7.1 R23.2
N21267797: C19.1 L5.1 R19.2
N21267893: C20.2 C22.1
N21267903: C20.1 L5.2 L6.1
N21267907: C22.2 L7.2 L8.1
N21267936: C17.1 L6.2
N21267939: C24.1 L8.2
N21306634: C226.2 R182.2 R183.1 U19.9(ADJ)
N21310593: C153.2 U7.42(VBIASVCO2)
N21313753: C128.2 J22.1(CENTER) R91.1 R93.2 R184.2
N21313758: C135.2 R93.1 R96.1 R185.1
N21321417: C137.1 L9.1 R97.2 R99.1
N21321463: C136.1 R97.1 U7.37(RFOUTAP)
N21321475: C140.1 R99.2 U7.36(RFOUTAM)
N21324767: R92.2 R184.1 Y1.5(COUTF)
N21324772: R94.2 R185.2 Y1.4(OUTF)
N21375599: C142.1 L10.1 R100.2 R104.1
N21375615: C138.1 R100.1 U7.30(RFOUTBP)
N21375619: C144.1 R104.2 U7.29(RFOUTBM)
N21375683: C138.2 J26.1(CENTER)
N21375685: C144.2 J27.1(CENTER)
N21382849: C154.2 U7.53(VBIASVRAC)
N21382882: C152.2 U7.44(VREFVCO2)
N21382945: C150.1 U7.56(VREFVCO)
N21382968: C148.2 U7.59(VREGVCO)
N21391760: C147.2 U7.14(VREGIN)
N21391777: C151.2 U7.7(VBIASVCO)
N21397866: C139.1 R98.2 U7.34(VCCBUF)
N21398145: C141.1 R101.2 U7.11(VCCDIG)
N21398455: C143.1 R103.2 U7.21(VCCCP)
N21398481: C145.1 R106.2 U7.25(VCCMASH)
N21398674: C146.1 R108.2 U7.57(VCCVCO)
N21398700: C149.1 R109.2 U7.41(VCCVCO2)
N21435177: R168.2 R169.2
N21445987: J28.C39 J28.D36 J28.D38 J28.D40 R115.1
N21446161: J28.D1 J29.1
N21451420: C53.1 R61.1 U6.26(Q3)
N21451422: C54.1 R62.1 U6.25(Q\3\)
N21451444: C57.1 R67.1 U6.24(Q4)
N21451446: C58.1 R68.1 U6.23(Q\4\)
N21451502: C62.1 R78.1 U6.19(Q\6\)
N21451579: JP10.2(PIN2) U6.2(CLK_SEL)
N21451692: R79.2 R82.1 U6.6(CLK1)
N21451698: R79.1 R83.1 U6.7(C\L\K\1\)
N21453692: C210.1 FB6.1 R177.1 U17.3(VOUT)
N21453823: R177.2 R179.1 U17.14(FB)
N21482374: J34.1 R178.2 U17.5(S\H\U\T\D\O\W\N\)
N21491465: R130.2 R131.1 U9.6(A4)
N21491508: R128.2 R129.1 U9.5(A3)
N21491543: R120.2 R121.1 U9.4(A2)
N21491580: R116.2 R117.1 U9.3(A1)
N21491663: R126.2 R127.1
N21491825: R122.1 U9.14(B1)
N21491829: R123.1 U9.13(B2)
N21491833: R124.1 U9.12(B3)
N21491837: R119.2 R125.1 U9.11(B4)
N21491881: R126.1 U9.9(OEB)
N21538078: C16.1 R20.1 R21.1
N21540492: R70.2 R73.1 U6.3(CLK0)
N21540508: R70.1 R75.1 U6.4(C\L\K\0\)
N21563907: C61.1 R77.1 U6.20(Q6)
N21564155: C60.1 R72.1 U6.21(Q\5\)
N21564157: C59.1 R71.1 U6.22(Q5)
N21594563: TP16.1(TP) U17.6(E\R\R\O\R\)
N21602890: J24.1 Y1.1(OE)
N21623803: R192.1 U12.52(DDBUS1)
N21623805: R191.1 U12.54(DDBUS3)
N21623807: R193.1 U12.48(DDBUS0)
N21623845: R155.1 U12.53(DDBUS2)
N21637810: D10.1(ANODE) R188.2
N21637823: R188.1 U20.1(P1.0/TA0.1/DMAE0)
N21637881: SW1.2 U20.2(P1.1/TA0.2)
N21638540: J35.1 U20.9(P1.3/TA1.2)
N21638545: J35.2 R189.1 TP17.1(TP) U21.2(VN) U22.2(VN)
N21638708: JP13.1(PIN1) U20.11(P1.5/TB0.2)
N21638717: JP12.1(PIN1) U20.10(P1.4/TB0.1)
N21648189: JP12.2(PIN2) TP18.1(TP) U21.1(VP)
N21648194: JP13.2(PIN2) TP19.1(TP) U22.1(VP)
N21648707: C233.1 R187.2 U20.48(AVCC)
N21648712: C231.2 C232.2 C233.2 R186.2 U20.44(AVSS#44) U20.47(AVSS#47)
N21649143: C231.1 U20.46(PJ.5/LFXOUT) Y3.1
N21649147: C232.1 U20.45(PJ.4/LFXIN) Y3.2
N21650021: C235.1 U20.42(PJ.6/XFZIN) Y4.2
N21650025: C234.1 U20.43(PJ.7/ZFXOUT) Y4.1
N21650057: C234.2 C235.2 U20.41(AVSS#41)
N216554902: SW3.2 SW3.4 SW3.5

Pads without a net: J28 A2 A3 A6 A7 A10 A11 A14 A15 A18 A19 A22 A23 A26 A27 A30 A31 A34 A35 A38 A39 B1 B4 B5 B8 B9 B12 B13 B16 B17 B20 B21 B24 B25 B28 B29 B32 B33 B36 B37 B40 C2 C3 C6 C7 C18 C19 C20 D4 D5 D17 D18 D19 D29 D33 D34 E8 E12 E13 E14 E15 E16 E18 E19 E33 E34 E36 E37 F6 F16 F17 F19 F20 F34 F35 F37 F38 G2 G3 G17 G34 H1 H4 H5 H6 H15 H18 H20 J2 J3 J4 J16 J17 J18 J19 J21 J22 J23 J33 J34 J36 J37 K1 K2 K4 K5 K12 K16 K17 K19 K20 K22 K23 K34 K35 K37 K38; J32 4; J36 2 6 10 12 13 14; NOREF#4 1; NOREF#6 1; NOREF#15 1; NOREF#18 1; NOREF#20 1; NOREF#22 1; T1 2; U6 11 12 13 14 15 16 29 30 31 32 33 34; U7 1 2 33 46 47 48 49 50 52 58 62 63 64; U8 7; U10 4; U12 21 22 23 24 30 32 33 34 36 44 45 46 55 57 58 59 60; U13 6 7; U14 1 3; U17 2 4 7 10 12 13; U18 5; U19 5; U20 3 4 5 6 7 8 16 17 18 19 24 25 26 27 28 29 30 31 32 33 34 35 38; Y1 2

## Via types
v1: diameter 0.457, hole 0.203, TOP to BOTTOM, 1297 vias
v2: diameter 0.508, hole 0.254, TOP to BOTTOM, 2337 vias
v3: diameter 0.559, hole 0.305, TOP to BOTTOM, 62 vias
v4: diameter 0.356, hole 0.152, TOP to BOTTOM, 387 vias
v5: diameter 0.406, hole 0.203, TOP to BOTTOM, 86 vias
v6: diameter 0.762, hole 0.381, TOP to BOTTOM, 128 vias

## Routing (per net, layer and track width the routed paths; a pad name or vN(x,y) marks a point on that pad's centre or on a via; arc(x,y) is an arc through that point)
1V9A: length 5.9
  BOTTOM w0.305: C87.1 v1(71.25,91.06) ; C94.1 v1(80.14,77.09) ; C90.1 v1(71.25,78.36) ; C88.1 v1(75.06,82.17) ; C95.1 v1(81.41,77.09) ; C93.1 v1(77.6,73.28) ; C85.1 v1(71.25,92.33) ; C78.1 v1(77.6,96.14) ; C84.1 v1(71.25,93.6) ; C86.1 v1(75.06,88.52) ; C82.1 v1(80.14,93.6) ; C81.1 v1(78.87,94.87) ; C92.1 v1(77.6,74.55) ; C91.1 v1(72.52,73.28) ; C83.1 v1(81.41,93.6) ; C79.1 v1(77.6,97.41) ; C89.1 v1(71.25,79.63) ; C80.1 v1(72.52,97.41)
  vias: v2(72.01,48.9) v2(72.01,47.88) v2(72.01,46.74) v2(73.15,48.9) v2(73.15,47.88) v2(73.15,46.74) v2(74.17,48.9) v2(74.17,47.88) v2(74.17,46.74)
1V9DR: length 5.3
  BOTTOM w0.305: C103.1 v1(95.38,87.25) ; C107.1 v1(83.95,73.28) ; C101.1 v1(91.57,93.6) ; C108.1 v1(89.03,77.09) ; C111.1 v1(95.38,79.63) ; C110.1 v1(89.03,73.28) ; C106.1 v1(83.95,77.09) ; C100.1 v1(89.03,93.6) ; C105.1 v1(91.57,78.36) ; C97.1 83.97,97.43 v1(83.95,97.41) ; C109.1 v1(90.3,77.09) ; C98.1 v1(83.95,93.6) ; C102.1 v1(91.57,87.25) ; v1(91.77,79.8) 91.57,79.8 U4.R17 C104.1 ; C99.1 v1(89.03,97.41)
  vias: v1(90.55,92.63) v1(92.84,94.87) v2(86.23,48.64) v2(86.23,47.62) v2(86.23,46.61) v2(87.38,48.64) v2(87.38,47.62) v2(87.38,46.61) v2(88.52,48.64) v2(88.52,47.62) v2(88.52,46.61) v2(89.66,48.64) v2(89.66,47.62) v2(89.66,46.61)
1V9E: length 2
  BOTTOM w0.305: C121.1 81.38,74.52 v1(81.41,74.55) ; C117.1 v1(80.14,97.41) ; C120.1 80.16,75.79 v1(80.14,75.82) ; C118.1 v1(81.41,96.14) ; C119.1 v1(80.14,94.87) ; C122.1 v1(80.14,73.28)
  vias: v2(78.49,48.64) v2(78.49,47.62) v2(78.49,46.61) v2(79.63,48.64) v2(79.63,47.62) v2(79.63,46.61) v2(80.64,48.64) v2(80.64,47.62) v2(80.64,46.61)
1V9TC: length 4.6
  BOTTOM w0.305: C68.1 v1(73.79,84.71) ; C69.1 v1(73.79,83.44) ; C64.1 v1(71.25,89.79) ; C66.1 v1(73.79,87.25) ; C74.1 v1(73.79,79.63) ; C73.1 v1(75.06,80.9) ; C67.1 v1(73.79,85.98) ; C65.1 v1(72.52,88.52) ; C75.1 v1(75.06,79.63) ; C76.1 v1(75.06,89.79) ; C70.1 v1(72.52,82.17) ; C71.1 v1(73.79,80.9) ; C63.1 v1(73.79,89.79) ; C72.1 v1(71.25,80.9)
  vias: v2(65.28,48.77) v2(65.28,47.75) v2(65.28,46.74) v2(66.29,48.77) v2(66.29,47.75) v2(66.29,46.74) v2(67.31,48.77) v2(67.31,47.75) v2(67.31,46.74)
3.3VLMX:
  vias: v2(10.29,77.98) v2(10.29,76.96) v2(10.29,75.95) v2(11.43,77.98) v2(11.43,76.96) v2(11.43,75.95) v2(12.83,77.98) v2(12.83,76.96) v2(12.83,75.95) v2(14.02,114.15) v2(14.02,113.13) v2(14.02,112.12) v2(13.97,77.98) v2(13.97,76.96) v2(13.97,75.95) v2(15.16,114.15) v2(15.16,113.13) v2(15.16,112.12) v2(15.24,77.98) v2(15.24,76.96) v2(15.24,75.95) v2(16.43,114.15) v2(16.43,113.13) v2(16.43,112.12) v2(18.34,114.15) v2(18.34,113.13) v2(18.34,112.12) v2(19.61,114.15) v2(19.61,113.13) v2(19.61,112.12) v2(20.75,114.15) v2(20.75,113.13) v2(20.75,112.12)
5.0V_IN:
  vias: v2(11.56,21.97) v2(11.56,20.95) v2(11.56,19.81) v2(12.57,21.97) v2(12.57,20.95) v2(12.57,19.81) v2(13.72,21.92) v2(13.72,20.9) v2(13.72,19.76) v2(14.99,21.97) v2(14.99,20.95) v2(14.99,19.81) v2(16.13,21.97) v2(16.13,20.95) v2(16.13,19.81)
5VIN: length 31.9
  TOP w0.305: v1(103.38,20.95) 103.38,9.4 v2(101.35,7.37) ; 51.5,5.28 51.32,5.46 51.32,5.58 49.66,7.24 R161.1
  vias: v2(4.57,63.12) v2(4.57,62.1) v2(4.57,59.94) v2(4.57,58.93) v2(4.57,57.91) v2(5.59,63.12) v2(5.59,62.1) v2(5.59,60.96) v2(5.59,59.94) v2(5.59,58.93) v2(5.59,57.91) v2(6.6,63.12) v2(6.6,62.1) v2(6.6,60.96) v2(6.6,59.94) v2(6.6,58.93) v2(6.6,57.91) v2(29.31,16.26) v2(29.31,14.99) v2(29.31,13.72) v2(29.34,12.7) v2(29.34,11.68) v2(29.34,10.67) v2(30.33,16.26) v2(30.33,14.99) v2(30.33,13.72) v2(30.35,12.7) v2(30.35,11.68) v2(30.35,10.67) v2(31.09,18.67) v2(31.09,17.53) v2(31.34,16.26) v2(31.34,14.99) v2(31.34,13.72) v2(31.37,12.7) v2(31.37,11.68) v2(31.37,10.67) v2(32.1,18.67) v2(32.1,17.53) v2(32.36,16.26) v2(32.36,14.99) v2(32.36,13.72) v2(32.38,12.7) v2(32.38,11.68) v2(32.38,10.67) v2(32.99,17.53) v2(33.15,18.92) v2(33.37,14.1) v2(33.4,13.08) v2(33.4,12.06) v2(35.69,4.7) v2(35.69,3.68) v2(35.69,2.67) v2(36.7,4.7) v2(36.7,3.68) v2(36.7,2.67) v2(37.72,4.7) v2(37.72,3.68) v2(37.72,2.67) v2(38.73,4.73) v2(38.73,3.71) v2(38.73,2.69) v2(39.88,4.7) v2(39.88,3.68) v2(39.88,2.67) v2(40.89,4.73) v2(40.89,3.71) v2(40.89,2.69) v2(57.4,6.35) v2(57.4,5.21) v2(57.4,4.06) v2(57.4,3.05) v2(57.4,2.03) v2(58.42,6.35) v2(58.42,5.21) v2(58.42,4.06) v2(58.42,3.05) v2(58.42,2.03) v2(59.44,6.35) v2(59.44,5.21) v2(59.44,4.06) v2(59.44,3.05) v2(59.44,2.03) v2(99.31,8.51) v2(99.31,7.37) v2(99.31,6.22) v2(99.31,5.21) v2(99.31,4.19) v2(99.82,9.27) v2(100.33,8.51) v2(100.33,7.37) v2(100.33,6.22) v2(100.33,5.21) v2(100.33,4.19) v2(101.35,6.22) v2(101.35,5.21) v2(101.35,4.19)
+2.5V: length 3.3
  BOTTOM w0.305: v4(99.77,121.92) C44.1 100.1,121.59 100.18,121.59 ; v4(95.33,121.18) 95.33,121.23 94.95,121.61 ; v4(95.33,121.92) 95.07,121.67 C45.1 ; 94.95,121.61 C45.1 ; 94.95,121.61 94.69,121.36 v4(94.69,121.18) ; v1(100.2,121.59) 100.18,121.59 ; 100.18,121.59 v4(99.77,121.18) ; C45.1 v4(94.69,121.92) ; C47.2 v4(94.69,120.47)
  vias: v2(100.33,33.15) v2(100.28,32.13) v2(100.28,30.96) v2(100.28,29.87) v2(101.24,32.11) v2(101.24,30.94) v2(101.24,29.84) v2(101.3,33.12) v2(102.23,32.13) v2(102.23,30.96) v2(102.23,29.87) v2(102.29,33.15) v2(103.15,32.13) v2(103.15,30.96) v2(103.15,29.87) v2(103.2,33.15) v4(89.51,116.74) v4(89.51,111.66) v4(90.25,116.74) v4(90.25,111.66) v4(90.96,116.74) v4(90.96,111.66) v4(94.69,107.95) v4(94.69,107.21) v4(94.69,106.5) v4(95.33,120.47) v4(99.14,107.95) v4(99.14,107.21) v4(99.14,106.5) v4(99.77,120.47) v4(99.77,107.95) v4(99.77,107.21) v4(99.77,106.5) v4(103.5,116.74) v4(104.24,116.74) v4(104.95,116.74)
+3.3V_LMX:
  vias: v2(13.39,122.53) v2(13.51,120.37) v2(13.51,119.35) v2(13.51,118.34) v2(14.48,122.56) v2(14.53,122.53) v2(14.63,120.37) v2(14.63,119.35) v2(14.63,118.34) v2(14.66,121.51) v2(17.14,129.29) v2(21.46,146.66) v2(22.86,146.93) v2(23.19,118.57) v2(23.98,146.84) v2(25.78,120.12) v2(26.04,146.65) v2(27.13,137.72) v2(29.29,120.09) v2(35,130.78) v2(35.05,128.78)
+3.3V_LMXRF: length 26.9
  TOP w0.279: L9.2 27.43,115.39 27.8,115.03 29.07,115.03 39.42,125.38 L10.2
  TOP w0.305: v1(23.47,115.27) 24.1,115.9 L9.2
  BOTTOM w0.279: FB9.2 23.5,113.08 C222.1 26.16,113.08 C223.1
  BOTTOM w0.305: FB9.2 v1(23.47,115.27)
+4.8V_LMH:
  vias: v2(40.51,30.35) v2(40.51,29.21) v2(40.51,28.07) v2(41.66,30.35) v2(41.66,29.21) v2(41.66,28.07) v2(42.8,30.35) v2(42.8,29.21) v2(42.8,28.07) v2(43.94,30.35) v2(43.94,29.21) v2(43.94,28.07) v2(50.01,89.28) v2(52.6,68.35) v2(52.65,102.31) v2(53.21,102.95) v2(53.24,67.79) v2(56.49,106.15) v2(56.49,64.54) v2(57.05,63.96) v2(57.07,106.71) v4(50.83,69.88) v4(50.9,100.91) v4(51.28,70.33) v4(51.28,69.42) v4(51.35,101.37) v4(51.36,100.46) v4(51.74,69.88) v4(51.71,68.99) v4(51.79,101.8) v4(51.81,100.91) v4(52.25,101.35) v4(52.17,69.44) v4(57.45,107.67) v4(57.56,62.97) v4(57.91,108.12) v4(57.94,107.21) v4(58.04,63.43) v4(58.01,62.51) v4(58.34,108.56) v4(58.39,107.67) v4(58.45,62.08) v4(58.47,63) v4(58.83,108.1) v4(58.9,62.56)
GND: length 17.5
  TOP w0.279: C141.2 v1(26.29,134.52)
  TOP w0.305: v2(26.38,31.26) 26.19,31.45 C170.2
  TOP w0.381: v1(70.54,76.61) 71.02,77.09 U4.U1
  TOP w0.508: D10.2 14.22,101.7 v3(14.43,101.9) ; v1(17.25,125.48) C154.1 v1(18.21,124.61) ; v3(15.42,102.9) 15.52,103 R186.1
  L11_GND6 w0.203: 123.87,97.99 123.88,97.99 123.9,97.99 ; 123.9,97.28 123.88,97.28 123.87,97.28
  BOTTOM w0.102: v1(90.63,80.16) C104.2
  BOTTOM w0.279: U7.10 v1(26.79,134.84)
  BOTTOM w0.305: C109.2 v1(91.57,77.09) ; C68.2 v1(75.06,84.71) ; C120.2 81.38,75.79 v1(81.41,75.82) ; C63.2 v1(72.52,89.79) ; C108.2 89.03,78.31 v1(89,78.33) ; C119.2 v1(81.41,94.87) ; C105.2 v1(90.32,78.36) ; C100.2 v1(90.3,93.6) ; C117.2 v1(81.41,97.41) ; C121.2 80.16,74.52 v1(80.14,74.55) ; C69.2 v1(72.52,83.44) ; C122.2 v1(81.41,73.28) ; C66.2 v1(72.52,87.25) ; C91.2 v1(71.25,73.28) ; C118.2 v1(80.14,96.14) ; C93.2 v1(78.87,73.28) ; C74.2 v1(72.52,79.63) ; C101.2 v1(91.57,92.33) ; C65.2 v1(73.79,88.52) ; R51.2 v1(72.52,74.55) ; C80.2 v1(71.25,97.41) ; C79.2 v1(78.87,97.41) ; C114.2 v1(71.25,84.71) ; C81.2 v1(77.6,94.87) ; C71.2 v1(72.52,80.9) ; C92.2 v1(78.87,74.55) ; C67.2 v1(75.06,85.98) ; C126.2 v1(71.25,85.98) ; C78.2 v1(78.87,96.14) ; C90.2 v1(72.52,78.36)
  BOTTOM w0.381: v2(54.87,64.41) 54.79,64.49 R28.2
  vias: v1(17.04,67.08) v1(18.95,62.48) v1(19.2,142.01) v1(20.29,143.1) v1(20.32,140.87) v1(21.33,45.92) v1(21.39,47.32) v1(21.36,43.34) v1(22.61,115.32) v1(24.08,39.12) v1(26.21,49.76) v1(26.29,117.98) v1(26.39,113.92) v1(26.44,61.34) v1(27.18,119.48) v1(27.71,65.2) v1(28.7,41.45) v1(29.11,119.41) v1(30.3,118.72) v1(31.7,49.76) v1(32.61,47.35) v1(32.61,44.83) v1(35.79,127.61) v1(35.76,125.88) v1(38.38,95.55) v1(38.38,81.61) v1(38.38,68.86) v1(39.45,67.72) v1(39.52,96.62) v1(39.5,94.39) v1(39.5,82.65) v1(40.61,81.53) v1(40.61,68.83) v1(40.64,27.25) v1(44.86,143.76) v1(45.95,144.88) v1(47.09,143.74) v1(52.25,32.02) v1(53.09,32.02) v1(54.61,132.56) v1(54.58,130.33) v1(55.73,131.34) v1(57.89,32.03) v1(58.58,32.03) v1(59.25,32.03) v1(61.42,88.8) v1(62.26,87.99) v1(65,80.31) v1(68.28,83.62) v1(68.58,87.83) v1(68.61,82.96) v1(70.28,105.87) v1(70.31,93.6) v1(70.31,92.33) v1(70.31,91.06) v1(70.31,89.79) v1(70.31,80.9) v1(70.31,79.63) v1(70.76,57.43) v1(71.65,105.87) v1(71.88,58.52) v1(71.88,56.29) v1(72.52,96.14) v1(72.52,91.06) v1(73.79,82.17) v1(73.79,78.36) v1(75.06,93.6) v1(75.06,92.33) v1(75.06,78.36) v1(75.06,77.09) v1(76,89.79) v1(76,88.52) v1(76,87.25) v1(76,83.44) v1(76,82.17) v1(76,80.9) v1(76,79.63) v1(76.07,91.03) v1(76.33,93.6) v1(76.33,77.09) v1(77.85,8.59) v1(78.31,89.34) v1(78.31,88.34) v1(78.31,87.34) v1(78.31,86.34) v1(78.31,85.34) v1(78.31,84.34) v1(78.31,83.34) v1(78.31,82.34) v1(78.31,81.34) v1(78.31,80.34) v1(78.87,92.66) v1(78.87,78.03) v1(79.31,90.34) v1(79.31,89.34) v1(79.31,88.34) v1(79.31,87.34) v1(79.31,86.34) v1(79.31,85.34) v1(79.31,84.34) v1(79.31,83.34) v1(79.31,82.34) v1(79.31,81.34) v1(79.31,80.34) v1(79.55,116.28) v1(79.55,113.59) v1(79.55,111.18) v1(79.6,108.56) v1(80.14,92.66) v1(80.14,78.03) v1(80.31,90.34) v1(80.31,89.34) v1(80.31,88.34) v1(80.31,87.34) v1(80.31,86.34) v1(80.31,85.34) v1(80.31,84.34) v1(80.31,83.34) v1(80.31,82.34) v1(80.31,81.34) v1(80.31,80.34) v1(81.25,98.68) v1(81.31,90.34) v1(81.31,89.34) v1(81.31,88.34) v1(81.31,87.34) v1(81.31,86.34) v1(81.31,85.34) v1(81.31,84.34) v1(81.31,83.34) v1(81.31,82.34) v1(81.31,81.34) v1(81.31,80.34) v1(81.41,92.66) v1(81.41,78.03) v1(81.64,71.86) v1(82.17,133.55) v1(82.19,105.97) v1(82.19,102.87) v1(82.31,90.34) v1(82.31,89.34) v1(82.31,88.34) v1(82.31,87.34) v1(82.31,86.34) v1(82.31,85.34) v1(82.31,84.34) v1(82.31,83.34) v1(82.31,82.34) v1(82.31,81.34) v1(82.31,80.34) v1(82.52,109.65) v1(82.52,100.84) v1(82.6,127.25) v1(83.31,90.34) v1(83.31,89.34) v1(83.31,88.34) v1(83.31,87.34) v1(83.31,86.34) v1(83.31,85.34) v1(83.31,84.34) v1(83.31,83.34) v1(83.31,82.34) v1(83.31,81.34) v1(83.31,80.34) v1(83.95,104.27) v1(83.95,102.08) v1(83.95,92.66) v1(83.95,78.03) v1(83.95,72.34) v1(83.97,108.13) v1(83.97,98.35) v1(84.31,90.34) v1(84.31,89.34) v1(84.31,88.34) v1(84.31,87.34) v1(84.31,86.34) v1(84.31,85.34) v1(84.31,84.34) v1(84.31,83.34) v1(84.31,82.34) v1(84.31,81.34) v1(84.31,80.34) v1(84.48,56.29) v1(84.61,58.52) v1(84.91,71.35) v1(85.06,118.87) v1(85.17,133.17) v1(85.31,90.34) v1(85.31,89.34) v1(85.31,88.34) v1(85.31,87.34) v1(85.31,86.34) v1(85.31,85.34) v1(85.31,84.34) v1(85.31,83.34) v1(85.31,82.34) v1(85.31,81.34) v1(85.31,80.34) v1(85.6,109.42) v1(85.7,57.4) v1(86.03,114.25) v1(86.26,110.87) v1(86.31,100.76) v1(86.31,90.34) v1(86.31,89.34) v1(86.31,88.34) v1(86.31,87.34) v1(86.31,86.34) v1(86.31,85.34) v1(86.31,84.34) v1(86.31,83.34) v1(86.31,82.34) v1(86.31,81.34) v1(86.31,80.34) v1(86.49,97.41) v1(86.49,93.6) v1(86.49,77.09) v1(86.49,73.28) v1(86.79,108.13) v1(87.22,72.36) v1(87.31,90.34) v1(87.31,89.34) v1(87.31,88.34) v1(87.31,87.34) v1(87.31,86.34) v1(87.31,85.34) v1(87.31,84.34) v1(87.31,83.34) v1(87.31,82.34) v1(87.31,81.34) v1(87.31,80.34) v1(87.43,114.2) v1(87.48,116.08) v1(87.45,112.29) v1(87.73,104.27) v1(87.73,101.88) v1(88.31,90.34) v1(88.31,89.34) v1(88.31,88.34) v1(88.31,87.34) v1(88.31,86.34) v1(88.31,85.34) v1(88.31,84.34) v1(88.31,83.34) v1(88.31,82.34) v1(88.31,81.34) v1(88.31,80.34) v1(88.42,143.41) v1(88.42,140.46) v1(88.52,109.73) v1(89.03,98.35) v1(89.03,72.34) v1(89.08,70.36) v1(89.64,105.36) v1(90.42,65.61) v1(90.53,101.9) v1(90.55,92.02) v1(90.78,104.32) v1(90.88,107.06) v1(90.93,87.86) v1(91.41,48.84) v1(91.57,116.74) v1(91.57,111.66) v1(91.57,97.41) v1(91.57,91.06) v1(91.57,83.44) v1(91.57,73.28) v1(92,70.97) v1(92.2,63.88) v1(92.3,105.61) v1(92.84,75.82) v1(93.52,69.44) v1(93.62,44.75) v1(93.73,62.28) v1(94.11,103.86) v1(94.31,64.14) v1(94.56,119.86) v1(94.69,108.53) v1(94.69,43.59) v1(94.77,68.17) v1(94.79,45.82) v1(95.33,119.86) v1(95.38,97.41) v1(95.38,91.06) v1(95.38,83.44) v1(95.38,73.28) v1(95.86,62.43) v1(96.32,87.25) v1(96.32,79.63) v1(96.37,103.89) v1(96.55,83.64) v1(96.62,80.95) v1(96.62,64.14) v1(96.85,75.82) v1(96.9,72.57) v1(96.9,67.82) v1(97.1,94.87) v1(97.21,93.57) v1(97.28,100.53) v1(97.26,91.64) v1(97.38,88.49) v1(97.38,85.67) v1(97.99,60.68) v1(98.35,87.22) v1(98.27,85.24) v1(98.27,84.53) v1(98.32,83.26) v1(98.42,98.93) v1(98.5,62.51) v1(98.68,103.89) v1(98.7,64.49) v1(99.14,108.53) v1(99.42,100.36) v1(99.49,56.57) v1(99.77,119.86) v1(99.82,46.05) v1(99.9,108.53) v1(100.28,87.81) v1(100.41,85.27) v1(100.41,83.13) v1(100.61,74.88) v1(100.81,98.98) v1(100.91,103.86) v1(101.37,64.14) v1(101.37,59.94) v1(101.57,100.43) v1(101.57,62.36) v1(101.96,109.25) v1(102.21,56.57) v1(102.36,106.38) v1(102.44,53.92) v1(102.64,77.09) v1(102.62,45.97) v1(102.67,96.88) v1(102.77,104.29) v1(102.9,116.74) v1(103.07,86.08) v1(103.23,83.06) v1(103.28,87.48) v1(103.53,64.19) v1(103.73,100.33) v1(103.73,62.41) v1(103.76,59.97) v1(104.01,106.38) v1(104.06,109.22) v1(104.44,88.93) v1(104.65,83.06) v1(104.9,96.04) v1(105,104.27) v1(105.16,56.62) v1(105.44,59.97) v1(105.36,53.92) v1(105.69,64.19) v1(105.89,62.41) v1(106.02,100.41) v1(106.2,107.39) v1(106.63,115.77) v1(106.63,113.89) v1(106.63,111.2) v1(106.63,109.32) v1(107.04,96.09) v1(107.19,104.24) v1(107.34,43.59) v1(107.39,117.81) v1(107.39,115.93) v1(107.39,113.74) v1(107.39,111.86) v1(107.39,106.4) v1(107.39,83.11) v1(107.37,45.82) v1(107.8,87.33) v1(107.87,64.19) v1(107.98,56.64) v1(108.1,115.85) v1(108.1,113.84) v1(108.1,100.43) v1(108.05,62.43) v1(108.31,111.48) v1(108.41,107.77) v1(108.56,44.7) v1(108.76,117.86) v1(108.79,88.85) v1(108.86,115.9) v1(109.02,103.28) v1(109.04,59.94) v1(109.17,96.11) v1(109.5,106.4) v1(109.55,115.29) v1(109.63,111.51) v1(110.01,64.19) v1(110.16,62.48) v1(110.24,53.9) v1(110.34,100.46) v1(110.52,114.27) v1(110.72,104.34) v1(110.85,59.89) v1(110.9,80.06) v1(111.28,57.05) v1(111.38,96.14) v1(111.66,113.08) v1(111.94,87.3) v1(112.17,64.16) v1(112.29,102.97) v1(112.37,100.51) v1(112.37,62.46) v1(112.6,107.95) v1(112.57,95.05) v1(113.06,80.72) v1(113.26,111.46) v1(113.36,57.07) v1(113.64,85.29) v1(114.17,81.05) v1(114.2,60.55) v1(114.2,55.55) v1(114.33,64.19) v1(114.45,102.95) v1(114.48,94.74) v1(114.5,62.43) v1(114.6,113.39) v1(114.55,100.46) v1(114.55,96.55) v1(114.71,81.66) v1(115.11,59.36) v1(115.44,111.46) v1(115.47,75.92) v1(115.65,87.5) v1(115.7,57.07) v1(115.87,82.96) v1(115.87,61.95) v1(116.48,70.33) v1(116.51,64.19) v1(116.56,77.01) v1(116.84,112.83) v1(116.87,100.51) v1(116.87,60.22) v1(117.12,107.95) v1(117.3,78.13) v1(117.37,58.55) v1(117.65,111.48) v1(117.65,87.76) v1(117.65,85.22) v1(117.68,65.43) v1(117.78,95.38) v1(117.81,75.92) v1(118.03,61.93) v1(118.26,109.68) v1(118.29,106.43) v1(118.39,79.22) v1(118.59,70.36) v1(118.64,64.19) v1(118.82,103) v1(118.8,53.77) v1(118.87,96.52) v1(118.95,88.8) v1(118.92,85.37) v1(118.92,83.11) v1(118.97,112.83) v1(119.1,60.17) v1(119.41,108.61) v1(119.63,94.72) v1(119.61,81.43) v1(119.71,83.26) v1(119.71,65.46) v1(119.89,105.16) v1(119.94,87.25) v1(119.86,75.92) v1(120.12,78.13) v1(120.09,55.6) v1(120.37,109.65) v1(120.8,70.33) v1(120.83,64.21) v1(120.9,107.9) v1(120.85,87.71) v1(121.01,104.09) v1(120.98,62.33) v1(121.11,53.85) v1(121.26,111.51) v1(121.41,91.24) v1(121.41,88.82) v1(121.67,100.58) v1(121.69,85.17) v1(121.77,113.31) v1(121.89,65.41) v1(122.05,56.01) v1(122.1,75.92) v1(122.07,58.5) v1(122.3,78.13) v1(122.76,85.8) v1(122.89,89.94) v1(123.01,98.63) v1(122.99,64.21) v1(123.29,101.27) v1(123.39,107.85) v1(123.47,109.42) v1(123.55,81.53) v1(123.77,61.01) v1(124.13,90.55) v1(124.1,89) v1(124.18,75.92) v1(124.16,65.41) v1(124.33,58.52) v1(124.46,78.13) v1(124.59,87.6) v1(124.76,113.31) v1(125.32,64.24) v1(125.27,62.23) v1(125.48,54.91) v1(125.48,53.31) v1(125.6,81.53) v1(125.68,105.84) v1(125.73,88.95) v1(125.78,107.7) v1(125.86,109.45) v1(125.86,99.92) v1(126.16,56.62) v1(126.26,78.11) v1(126.26,75.92) v1(126.26,73.69) v1(126.39,103) v1(126.42,61.04) v1(126.49,87.53) v1(126.62,93.45) v1(126.75,105.38) v1(126.97,58.55) v1(127.15,106.63) v1(127.2,97.49) v1(127.25,65.43) v1(127.41,94.84) v1(127.38,89.97) v1(127.38,72.62) v1(127.51,62.26) v1(127.56,113.33) v1(127.56,70.38) v1(127.71,85.83) v1(128.09,109.47) v1(128.19,89.15) v1(128.17,81.76) v1(128.32,107.54) v1(128.27,103.05) v1(128.5,91.54) v1(128.52,65.48) v1(128.65,105.41) v1(128.83,99.95) v1(128.78,97.76) v1(128.83,84.63) v1(128.88,68.05) v1(129.13,92.86) v1(129.11,69.39) v1(129.24,61.06) v1(129.24,58.52) v1(129.21,53.9) v1(129.44,62.31) v1(129.87,108.46) v1(129.95,94.31) v1(129.9,90.2) v1(130.15,105.36) v1(130.15,99.92) v1(130.18,103.05) v1(130.18,91.82) v1(130.25,97.92) v1(130.4,113.36) v1(130.94,109.17) v1(131.44,103.61) v1(131.44,99.8) v1(131.44,95.99) v1(131.44,88.37) v1(131.44,84.56) v1(131.44,80.75) v1(131.44,76.94) v1(131.44,73.13) v1(131.44,69.32) v1(131.44,65.51) v1(131.44,61.7) v1(131.44,57.89) v1(132.72,106.15) v1(132.72,101.07) v1(132.72,97.26) v1(132.72,93.45) v1(132.72,89.64) v1(132.72,82.02) v1(132.72,74.4) v1(132.72,70.59) v1(132.72,66.78) v1(132.72,62.97) v1(132.72,59.16) v1(132.72,56.62) v1(133.99,103.61) v1(133.99,95.99) v1(133.99,92.18) v1(133.99,80.75) v1(133.99,76.94) v1(133.99,73.13) v1(133.99,69.32) v1(133.99,65.51) v1(133.99,61.7) v1(133.99,57.89) v1(135.25,106.15) v1(135.25,102.34) v1(135.25,101.07) v1(135.25,97.26) v1(135.25,93.45) v1(135.25,89.64) v1(135.25,82.02) v1(135.25,78.21) v1(135.25,74.4) v1(135.25,70.59) v1(135.25,66.78) v1(135.25,62.97) v1(135.25,59.16) v1(135.25,56.62) v1(135.53,55.07) v1(136.17,110.44) v1(136.53,104.88) v1(136.53,103.61) v1(136.53,95.99) v1(136.53,92.18) v1(136.53,88.37) v1(136.53,84.56) v1(136.53,80.75) v1(136.53,76.94) v1(136.53,73.13) v1(136.53,69.32) v1(136.53,65.51) v1(136.53,61.7) v1(136.53,57.89) v1(137.79,106.15) v1(137.79,102.34) v1(137.79,101.07) v1(137.79,93.45) v1(137.79,85.83) v1(137.79,82.02) v1(137.79,78.21) v1(137.79,74.4) v1(137.79,70.59) v1(137.79,66.78) v1(137.79,62.97) v1(137.79,59.16) v1(137.79,56.62) v1(138.28,49.86) v1(139.12,113.26) v1(139.06,104.88) v1(139.06,103.61) v1(139.06,99.8) v1(139.06,98.53) v1(139.06,94.72) v1(139.06,90.91) v1(139.06,87.1) v1(139.06,79.48) v1(139.06,75.67) v1(139.06,71.86) v1(139.06,60.43) v1(139.06,57.89) v1(140.34,106.15) v1(140.34,102.34) v1(140.34,101.07) v1(140.34,97.26) v1(140.34,95.99) v1(140.34,92.18) v1(140.34,90.91) v1(140.34,87.1) v1(140.34,85.83) v1(140.34,80.75) v1(140.34,76.94) v1(140.34,75.67) v1(140.34,71.86) v1(140.34,70.59) v1(140.34,66.78) v1(140.34,65.51) v1(140.34,61.7) v1(140.34,59.16) v1(140.34,56.62) v1(141.58,113.26) v1(141.6,104.88) v1(141.6,103.61) v1(141.6,99.8) v1(141.6,98.53) v1(141.6,94.72) v1(141.6,93.45) v1(141.6,89.64) v1(141.6,88.37) v1(141.6,84.56) v1(141.6,83.29) v1(141.6,79.48) v1(141.6,78.21) v1(141.6,74.4) v1(141.6,73.13) v1(141.6,69.32) v1(141.6,68.05) v1(141.6,64.24) v1(141.6,62.97) v1(141.6,59.16) v1(141.6,57.89) v1(142.88,106.15) v1(142.88,102.34) v1(142.88,101.07) v1(142.88,97.26) v1(142.88,95.99) v1(142.88,92.18) v1(142.88,90.91) v1(142.88,87.1) v1(142.88,85.83) v1(142.88,82.02) v1(142.88,80.75) v1(142.88,76.94) v1(142.88,75.67) v1(142.88,71.86) v1(142.88,70.59) v1(142.88,66.78) v1(142.88,65.51) v1(142.88,61.7) v1(142.88,60.43) v1(142.88,56.62) v1(147.4,114.68) v2(0.64,151.76) v2(0.64,149.22) v2(0.64,146.69) v2(0.64,144.15) v2(0.64,141.6) v2(0.64,139.06) v2(0.64,136.53) v2(0.64,133.99) v2(0.64,131.44) v2(0.64,128.91) v2(0.64,126.36) v2(0.64,123.83) v2(0.64,121.28) v2(0.64,118.75) v2(0.64,116.2) v2(0.64,113.67) v2(0.64,111.12) v2(0.64,108.58) v2(0.64,106.05) v2(0.64,103.5) v2(0.64,100.97) v2(0.64,98.42) v2(0.64,95.89) v2(0.64,93.34) v2(0.64,90.81) v2(0.64,88.27) v2(0.64,85.72) v2(0.64,83.19) v2(0.64,80.64) v2(0.64,78.11) v2(0.64,75.56) v2(0.64,73.03) v2(0.64,70.48) v2(0.64,67.94) v2(0.64,65.41) v2(0.64,62.87) v2(0.64,60.33) v2(0.64,57.78) v2(0.64,55.24) v2(0.64,52.7) v2(0.64,50.16) v2(0.64,47.62) v2(0.64,45.09) v2(0.64,42.55) v2(0.64,40.01) v2(0.64,37.47) v2(0.64,34.92) v2(0.64,32.38) v2(0.64,29.84) v2(0.64,27.3) v2(0.64,24.77) v2(0.64,22.23) v2(0.64,19.68) v2(0.64,17.14) v2(0.64,14.61) v2(0.64,12.06) v2(0.64,9.53) v2(0.64,6.99) v2(0.64,4.45) v2(0.64,1.91) v2(0.89,0.64) v2(1.51,80.75) v2(1.63,52.2) v2(1.62,43.3) v2(1.64,41.85) v2(1.65,50.75) v2(1.8,7.98) v2(1.75,5.41) v2(1.91,10.85) v2(2.02,80) v2(2.57,51.46) v2(2.58,42.56) v2(2.79,151.76) v2(2.78,76.58) v2(2.8,75.67) v2(3,138.02) v2(2.97,15.88) v2(2.97,13.34) v2(3.07,145.82) v2(3.07,143.28) v2(3.07,140.74) v2(3.1,135.46) v2(3.1,132.92) v2(3.1,130.38) v2(3.1,127.84) v2(3.1,125.3) v2(3.23,122.2) v2(3.23,119.66) v2(3.23,117.12) v2(3.23,114.58) v2(3.23,112.04) v2(3.2,26.19) v2(3.2,23.65) v2(3.25,107.52) v2(3.25,104.98) v2(3.3,56.41) v2(3.3,53.87) v2(3.35,97.33) v2(3.35,94.79) v2(3.38,90.73) v2(3.38,88.19) v2(3.35,85.57) v2(3.35,83.03) v2(3.35,37.67) v2(3.35,35.13) v2(3.4,32.74) v2(3.43,0.64) v2(3.48,102.26) v2(3.48,99.72) v2(3.51,52.17) v2(3.51,50.72) v2(3.52,43.27) v2(3.52,41.82) v2(3.61,45.11) v2(3.66,47.68) v2(4.34,7.98) v2(4.29,5.41) v2(4.45,10.85) v2(5.21,151.6) v2(5.33,42.57) v2(5.46,51.36) v2(5.51,15.88) v2(5.51,13.34) v2(5.61,145.82) v2(5.61,143.28) v2(5.61,140.74) v2(5.71,35.03) v2(5.74,26.19) v2(5.74,23.65) v2(5.79,148.79) v2(5.84,56.41) v2(5.84,53.87) v2(5.94,136.19) v2(5.94,133.65) v2(5.94,129.54) v2(5.94,127) v2(5.92,90.73) v2(5.92,88.19) v2(5.89,85.57) v2(5.89,83.03) v2(5.97,0.64) v2(7.05,52.17) v2(7.05,43.29) v2(7.07,50.72) v2(7.07,41.84) v2(7.11,7.92) v2(7.06,5.36) v2(7.25,48.6) v2(7.19,33.91) v2(7.19,33.15) v2(7.52,15.04) v2(7.57,20.47) v2(7.57,17.93) v2(7.75,151.6) v2(7.77,123.29) v2(7.77,120.75) v2(7.77,118.21) v2(7.77,115.67) v2(7.77,113.13) v2(7.82,110.52) v2(7.92,90.75) v2(7.92,88.21) v2(7.9,85.6) v2(7.9,83.06) v2(8.12,62.73) v2(8.08,51.46) v2(8.08,49.68) v2(8.15,48.59) v2(8.08,42.58) v2(8.31,33.93) v2(8.31,33.15) v2(8.43,148.84) v2(8.43,146.3) v2(8.43,143.76) v2(8.43,141.22) v2(8.43,138.68) v2(8.53,136.12) v2(8.53,133.58) v2(8.53,131.04) v2(8.53,128.5) v2(8.53,125.96) v2(8.51,60.02) v2(8.51,57.48) v2(8.46,31.06) v2(8.46,28.52) v2(8.51,26.14) v2(8.51,23.6) v2(8.51,0.64) v2(8.61,61.98) v2(8.81,54.81) v2(8.81,52.27) v2(9.02,52.17) v2(9.02,50.72) v2(9.02,43.29) v2(9.02,41.84) v2(9.07,48.6) v2(9.14,44.55) v2(9.27,3.76) v2(10.11,20.47) v2(10.11,17.93) v2(10.06,15.04) v2(10.15,73.78) v2(10.31,123.29) v2(10.31,120.75) v2(10.31,118.21) v2(10.31,115.67) v2(10.31,113.13) v2(10.26,95.02) v2(10.26,92.48) v2(10.29,33.5) v2(10.39,41.68) v2(10.67,151.64) v2(10.72,71.45) v2(10.74,59.81) v2(10.73,57.81) v2(10.79,69.19) v2(10.77,66.57) v2(10.77,64.03) v2(10.9,110.01) v2(10.94,74.29) v2(10.97,148.84) v2(10.97,146.3) v2(10.97,143.76) v2(10.97,141.22) v2(10.97,138.68) v2(10.97,85.62) v2(10.97,83.08) v2(11,31.06) v2(11,28.52) v2(11.05,26.14) v2(11.05,23.6) v2(11.05,0.64) v2(11.07,136.12) v2(11.07,133.58) v2(11.07,131.04) v2(11.07,128.5) v2(11.07,125.96) v2(11.3,55.02) v2(11.3,52.48) v2(11.3,49.63) v2(11.38,118.14) v2(11.53,58.8) v2(11.81,3.76) v2(11.89,118.91) v2(11.94,36.86) v2(11.99,120.17) v2(12.27,121.56) v2(12.31,59.83) v2(12.3,57.8) v2(12.34,48.56) v2(12.83,33.5) v2(12.93,39.22) v2(12.93,38.23) v2(13,132.03) v2(12.95,127.38) v2(13.16,124.82) v2(13.18,70.9) v2(13.17,69.11) v2(13.26,151.6) v2(13.51,148.84) v2(13.51,146.3) v2(13.51,143.76) v2(13.51,141.22) v2(13.51,138.68) v2(13.61,42.95) v2(13.59,0.64) v2(13.79,44.6) v2(13.89,55.09) v2(13.89,49.71) v2(13.97,136.19) v2(14.05,109.91) v2(14.02,74.32) v2(14.02,71.78) v2(14.02,52.5) v2(13.97,37.06) v2(14.22,70) v2(14.53,96.75) v2(14.53,94.21) v2(14.58,129.79) v2(14.58,128.27) v2(14.58,3.71) v2(14.73,8.48) v2(14.73,5.94) v2(14.88,32.51) v2(15.26,70.92) v2(15.25,69.09) v2(15.27,43.33) v2(15.28,41.26) v2(15.54,132.03) v2(15.7,124.82) v2(15.93,45.42) v2(15.88,23.55) v2(15.98,78.74) v2(15.95,47.93) v2(16.05,148.84) v2(16.05,146.3) v2(16.05,143.76) v2(16.05,141.22) v2(16.05,138.68) v2(16.13,0.64) v2(16.15,37.01) v2(16.15,34.47) v2(16.26,56.77) v2(16.43,55.09) v2(16.43,49.71) v2(16.51,80.14) v2(16.56,151.6) v2(16.59,109.91) v2(16.56,52.5) v2(17.35,136.83) v2(17.35,134.29) v2(17.27,8.48) v2(17.27,5.94) v2(17.45,123.27) v2(17.45,120.73) v2(17.45,118.19) v2(17.45,115.65) v2(17.55,32.51) v2(17.78,19.79) v2(17.78,17.25) v2(17.83,14.86) v2(17.83,12.32) v2(18.29,85.6) v2(18.29,69.09) v2(18.64,49.68) v2(18.67,37.95) v2(18.69,34.47) v2(18.67,0.64) v2(18.95,148.89) v2(18.95,146.35) v2(19.1,151.6) v2(19.13,109.91) v2(19.35,107.04) v2(19.35,54.05) v2(19.35,51.51) v2(19.71,57.91) v2(19.71,56.39) v2(19.89,136.83) v2(19.89,134.29) v2(19.99,123.27) v2(19.99,120.73) v2(19.99,118.19) v2(19.99,115.65) v2(20.29,145.39) v2(20.45,129.31) v2(20.4,98.7) v2(20.4,96.16) v2(20.4,93.62) v2(20.45,91.31) v2(20.7,151.64) v2(20.65,43.79) v2(20.83,85.6) v2(20.88,31.32) v2(21.21,0.64) v2(21.31,69.55) v2(21.31,67.01) v2(21.43,63.75) v2(21.44,37.9) v2(21.46,148.23) v2(21.46,34.42) v2(21.89,54.05) v2(21.89,51.51) v2(22.07,118.57) v2(22.2,109.91) v2(22.25,63.75) v2(22.4,151.6) v2(22.58,149) v2(22.81,79.96) v2(22.81,77.42) v2(22.81,74.88) v2(22.81,72.03) v2(22.86,147.7) v2(22.94,98.7) v2(22.94,96.16) v2(22.94,93.62) v2(22.86,82.85) v2(23.08,63.75) v2(23.06,40.06) v2(23.06,29.03) v2(23.24,69.55) v2(23.24,67.01) v2(23.37,85.6) v2(23.44,41.58) v2(23.5,56.64) v2(23.75,0.64) v2(24,147.7) v2(24.31,119.61) v2(24.71,149) v2(24.74,109.91) v2(24.66,27.53) v2(24.94,151.6) v2(24.94,48.72) v2(25.15,117.12) v2(25.22,140.94) v2(25.25,114.66) v2(25.35,79.96) v2(25.35,77.42) v2(25.35,74.88) v2(25.35,72.03) v2(25.35,69.49) v2(25.35,66.95) v2(25.4,82.85) v2(25.48,98.7) v2(25.48,96.16) v2(25.48,93.62) v2(25.6,30.12) v2(25.65,41.78) v2(25.78,144.02) v2(25.78,123.7) v2(25.95,44.59) v2(26.29,139.57) v2(26.29,0.64) v2(26.42,141.86) v2(26.37,32.19) v2(26.97,25.1) v2(27.13,84.63) v2(27.1,56.95) v2(27.1,54.41) v2(27.1,37.49) v2(27.2,107.49) v2(27.28,109.91) v2(27.46,43.28) v2(27.94,82.85) v2(27.94,80.04) v2(27.94,77.5) v2(27.94,72.11) v2(27.94,69.57) v2(27.91,59.39) v2(27.97,112.32) v2(28.04,61.24) v2(28.04,30.12) v2(28.04,27.58) v2(28.07,74.9) v2(28.07,66.98) v2(28.24,151.6) v2(28.25,94.59) v2(28.24,87.27) v2(28.19,22.86) v2(28.19,21.97) v2(28.4,99.82) v2(28.4,97.28) v2(28.37,92.38) v2(28.37,89.79) v2(28.57,148.75) v2(28.57,115.7) v2(28.83,0.64) v2(28.91,48.62) v2(28.91,47.6) v2(29.18,42.8) v2(29.34,123.7) v2(29.59,141.86) v2(29.64,56.95) v2(29.64,54.41) v2(29.67,84.63) v2(29.92,110.03) v2(29.92,107.49) v2(29.92,104.95) v2(30,46.1) v2(30.05,5.82) v2(30.1,3) v2(30.23,144.02) v2(30.18,8.61) v2(30.38,140.89) v2(30.4,35.53) v2(30.48,80.04) v2(30.48,77.5) v2(30.48,72.11) v2(30.48,69.57) v2(30.61,148.84) v2(30.61,146.3) v2(30.61,74.9) v2(30.61,66.98) v2(30.63,25.68) v2(30.66,64.47) v2(30.66,59.39) v2(30.78,151.6) v2(30.81,102.39) v2(30.78,87.27) v2(30.78,61.24) v2(30.84,33.17) v2(30.84,30.63) v2(30.84,28.09) v2(30.94,99.82) v2(30.94,97.28) v2(30.94,94.74) v2(30.91,92.38) v2(30.91,89.79) v2(30.89,22.43) v2(30.89,20.29) v2(31.37,0.64) v2(31.57,123.16) v2(31.57,120.62) v2(31.7,36.63) v2(31.88,138.68) v2(31.88,136.14) v2(31.9,46.28) v2(32.21,84.63) v2(32.23,57.02) v2(32.31,114.5) v2(32.36,54.43) v2(32.46,110.03) v2(32.46,107.49) v2(32.46,104.95) v2(32.59,5.82) v2(32.64,3) v2(32.72,8.61) v2(33.02,80.04) v2(33.02,77.5) v2(33.02,72.11) v2(33.02,69.57) v2(33.15,145.67) v2(33.15,143.13) v2(33.15,74.9) v2(33.15,66.98) v2(33.22,140.56) v2(33.2,64.47) v2(33.2,59.39) v2(33.22,25.76) v2(33.32,87.27) v2(33.32,61.24) v2(33.4,151.51) v2(33.35,102.39) v2(33.43,33.25) v2(33.43,30.71) v2(33.48,99.82) v2(33.48,97.28) v2(33.48,94.74) v2(33.45,92.38) v2(33.45,89.79) v2(33.48,22.5) v2(33.48,20.37) v2(33.63,115.11) v2(33.55,28.12) v2(33.66,116.03) v2(33.91,0.64) v2(34.19,41.02) v2(34.16,15.65) v2(34.26,10.52) v2(34.42,138.68) v2(34.42,136.14) v2(34.57,17.53) v2(34.67,116.03) v2(34.7,115.09) v2(34.7,107.54) v2(34.7,14.1) v2(34.77,57.02) v2(34.85,36.27) v2(34.87,112.7) v2(34.9,54.43) v2(35,104.95) v2(35.05,149.48) v2(35.08,124.87) v2(35.08,122.33) v2(35.26,110.08) v2(35.28,15.65) v2(35.36,39.67) v2(35.38,38.58) v2(35.38,14.71) v2(35.68,145.64) v2(35.69,143.13) v2(35.69,140.59) v2(35.71,97.31) v2(35.71,94.77) v2(35.66,10.41) v2(35.69,8.86) v2(35.79,77.32) v2(35.79,74.78) v2(35.79,64.54) v2(35.76,25.76) v2(35.89,72.8) v2(35.92,61.32) v2(35.92,59.41) v2(35.97,33.25) v2(35.97,30.71) v2(36.02,22.5) v2(36.07,102.49) v2(36.07,99.95) v2(36.09,28.12) v2(36.14,18.8) v2(36.14,17.88) v2(36.2,68.63) v2(36.17,14.1) v2(36.32,81) v2(36.27,39.65) v2(36.27,38.58) v2(36.42,117.6) v2(36.45,87.25) v2(36.37,15.62) v2(36.45,0.64) v2(36.58,129.9) v2(36.68,151.45) v2(36.7,9.63) v2(37.22,57.02) v2(37.16,18.8) v2(37.16,17.86) v2(37.31,104.95) v2(37.53,54.43) v2(37.53,51.99) v2(37.59,122.17) v2(37.59,119.63) v2(37.59,115.19) v2(37.59,112.65) v2(37.59,110.11) v2(37.59,107.57) v2(37.59,38.13) v2(37.72,10.41) v2(37.72,8.86) v2(37.97,130.05) v2(38.13,12.04) v2(38.23,149.48) v2(38.23,145.67) v2(38.23,143.13) v2(38.23,140.59) v2(38.18,17.5) v2(38.23,14.68) v2(38.25,134.24) v2(38.33,64.54) v2(38.3,25.76) v2(38.3,20.29) v2(38.43,78.08) v2(38.43,76.35) v2(38.43,70.79) v2(38.46,73.99) v2(38.46,61.32) v2(38.46,59.41) v2(38.51,33.25) v2(38.51,30.71) v2(38.61,102.49) v2(38.61,99.95) v2(38.63,28.12) v2(38.58,22.53) v2(38.61,9.32) v2(38.86,138.68) v2(38.86,136.14) v2(38.99,87.25) v2(39.04,39.5) v2(38.99,0.64) v2(39.22,151.45) v2(39.27,23.75) v2(39.29,21.77) v2(39.52,92.15) v2(39.62,127.25) v2(39.85,6.48) v2(40.13,122.17) v2(40.13,119.63) v2(40.13,115.19) v2(40.13,112.65) v2(40.13,110.11) v2(40.13,107.57) v2(40.16,22.73) v2(40.26,104.98) v2(40.26,57.02) v2(40.54,79.91) v2(40.54,78.08) v2(40.54,76.35) v2(40.51,74.02) v2(40.54,72.42) v2(40.46,47.88) v2(40.54,34.82) v2(40.56,101.73) v2(40.64,5.97) v2(40.74,31.7) v2(40.72,17.5) v2(40.67,12.04) v2(40.77,145.67) v2(40.77,143.13) v2(40.77,140.59) v2(40.77,127.25) v2(40.84,20.29) v2(40.77,14.68) v2(40.94,99.54) v2(40.87,64.54) v2(40.92,25.78) v2(41,61.32) v2(41,59.41) v2(40.97,23.72) v2(41,21.74) v2(41.15,9.32) v2(41.4,149.48) v2(41.4,138.68) v2(41.4,136.14) v2(41.4,133.6) v2(41.53,96.44) v2(41.5,94.56) v2(41.53,89.79) v2(41.53,87.25) v2(41.53,0.64) v2(41.66,151.51) v2(41.78,26.52) v2(41.91,17.53) v2(42.09,118.14) v2(42.32,52.81) v2(42.52,76.35) v2(42.49,74.02) v2(42.67,129.16) v2(42.72,116.18) v2(42.67,110.11) v2(42.67,107.57) v2(42.7,17.02) v2(42.8,104.98) v2(42.8,99.47) v2(42.9,45.47) v2(42.98,54.74) v2(43.05,14.91) v2(43.31,124.71) v2(43.38,96.44) v2(43.36,94.54) v2(43.51,101.83) v2(43.54,91.97) v2(43.46,64.54) v2(43.64,115.24) v2(43.59,61.32) v2(43.81,20.73) v2(43.94,149.48) v2(43.94,138.68) v2(43.94,136.14) v2(43.94,26.57) v2(43.97,55.73) v2(44.09,117.5) v2(44.07,89.79) v2(44.07,87.25) v2(44.07,0.64) v2(44.17,151.45) v2(44.32,53.37) v2(44.35,33.02) v2(44.42,25.81) v2(44.45,84.58) v2(44.45,82.04) v2(44.45,79.12) v2(44.48,43.28) v2(44.58,131.06) v2(44.7,76.35) v2(44.68,74.02) v2(44.7,71.37) v2(44.7,68.83) v2(44.7,65.91) v2(44.75,114.17) v2(44.81,112.22) v2(44.83,47.52) v2(44.75,39.37) v2(44.81,36.55) v2(44.91,56.72) v2(44.93,51.61) v2(45.01,116.59) v2(45.1,58.56) v2(45.09,31.01) v2(45.21,126.62) v2(45.21,110.11) v2(45.21,107.57) v2(45.19,88.7) v2(45.29,96.47) v2(45.31,94.54) v2(45.29,54.36) v2(45.62,111.41) v2(45.85,124.71) v2(45.85,122.17) v2(45.85,119.63) v2(45.91,59.36) v2(45.97,101.85) v2(45.97,99.31) v2(46.08,91.97) v2(46.15,115.44) v2(46.18,90.04) v2(46.23,55.32) v2(46.25,64.64) v2(46.38,61.42) v2(46.48,149.48) v2(46.48,132.97) v2(46.48,128.52) v2(46.61,29.95) v2(46.61,0.64) v2(46.71,151.45) v2(46.79,110.31) v2(46.89,45.64) v2(46.99,84.58) v2(46.99,82.04) v2(46.99,79.12) v2(47.14,76.33) v2(47.12,73.99) v2(47.14,39.47) v2(47.19,114.43) v2(47.24,71.37) v2(47.24,68.83) v2(47.24,65.91) v2(47.17,60.55) v2(47.19,56.24) v2(47.27,87.25) v2(47.27,36.63) v2(47.42,48.26) v2(47.62,107.87) v2(47.62,96.44) v2(47.65,94.54) v2(47.75,126.62) v2(47.93,109.25) v2(47.95,113.75) v2(48.16,57.12) v2(48.31,92) v2(48.34,61.72) v2(48.39,149.48) v2(48.39,139.32) v2(48.39,136.78) v2(48.39,124.71) v2(48.39,122.17) v2(48.39,119.63) v2(48.51,101.85) v2(48.51,99.31) v2(48.95,93.22) v2(49.02,134.87) v2(48.97,132.54) v2(49.02,128.52) v2(49.12,112.62) v2(49.12,95.81) v2(49.15,0.64) v2(49.43,87.27) v2(49.38,75.11) v2(49.38,72.54) v2(49.35,67.77) v2(49.4,58.29) v2(49.48,106.05) v2(49.45,64.69) v2(49.71,5.49) v2(49.81,2.74) v2(49.86,27.05) v2(50.01,151.45) v2(49.96,45.72) v2(49.96,43.18) v2(50.16,111.43) v2(50.16,97.71) v2(50.29,126.62) v2(50.29,117.73) v2(50.29,115.19) v2(50.27,91.92) v2(50.42,94.49) v2(50.44,29.62) v2(50.5,59.56) v2(50.6,48.23) v2(50.6,9.17) v2(50.7,23.77) v2(50.81,104.1) v2(50.8,82.17) v2(50.8,79.25) v2(50.83,51.59) v2(50.93,149.48) v2(50.93,146.94) v2(50.93,144.4) v2(50.93,141.86) v2(50.93,139.32) v2(50.93,136.78) v2(50.93,124.71) v2(50.93,122.17) v2(50.93,119.63) v2(50.86,66.61) v2(50.85,56.92) v2(50.85,54.43) v2(50.85,36.5) v2(51.16,14.66) v2(51.21,11.84) v2(51.28,17.45) v2(51.44,104.65) v2(51.45,66.07) v2(51.56,111.91) v2(51.74,93.19) v2(51.69,0.64) v2(51.77,90.45) v2(51.82,9.27) v2(51.82,8.36) v2(52.02,86.74) v2(52.32,26.04) v2(52.41,105.2) v2(52.43,65.49) v2(52.4,29.59) v2(52.4,27.05) v2(52.55,151.45) v2(52.55,72.57) v2(52.68,97.79) v2(52.65,48.26) v2(52.65,45.72) v2(52.65,43.18) v2(52.83,126.62) v2(52.83,117.73) v2(52.83,115.19) v2(52.83,112.75) v2(53.09,104.52) v2(53.11,66.17) v2(53.09,5.84) v2(53.24,91.72) v2(53.34,109.88) v2(53.27,106.1) v2(53.29,88.87) v2(53.34,82.17) v2(53.34,79.25) v2(53.29,64.59) v2(53.34,40.23) v2(53.37,60.81) v2(53.39,54.43) v2(53.37,51.59) v2(53.47,124.71) v2(53.47,122.17) v2(53.47,119.63) v2(53.47,27.56) v2(53.79,103.82) v2(53.81,66.87) v2(53.97,105.4) v2(53.99,65.29) v2(54.1,149.48) v2(54.1,146.94) v2(54.1,144.4) v2(54.1,141.86) v2(54.1,139.32) v2(54.1,136.78) v2(54.08,102.61) v2(54.05,94.51) v2(54.1,84.51) v2(54.1,76.17) v2(54.13,73.08) v2(54.09,68.05) v2(54.17,106.96) v2(54.18,96.16) v2(54.19,63.73) v2(54.2,27.08) v2(54.23,0.64) v2(54.36,5.84) v2(54.46,61.49) v2(54.61,134.11) v2(54.63,102) v2(54.56,87.66) v2(54.61,74.3) v2(54.73,107.93) v2(54.67,104.7) v2(54.67,68.68) v2(54.69,65.99) v2(54.71,62.79) v2(54.76,90.14) v2(54.85,106.28) v2(54.89,37.59) v2(54.97,93.9) v2(55.02,35.18) v2(55.07,76.86) v2(55.24,48.34) v2(55.24,45.8) v2(55.24,40.41) v2(55.24,29.72) v2(55.27,108.52) v2(55.27,62.19) v2(55.37,126.62) v2(55.37,117.73) v2(55.37,115.19) v2(55.37,112.65) v2(55.37,110.11) v2(55.6,151.45) v2(55.55,105.58) v2(55.57,65.11) v2(55.68,96.19) v2(55.7,86.51) v2(55.7,74.52) v2(55.83,42.72) v2(55.93,88.95) v2(56.01,124.71) v2(56.01,122.17) v2(56.01,119.63) v2(55.96,92.94) v2(55.98,77.77) v2(56.03,59.66) v2(55.98,54.51) v2(55.98,29.21) v2(56.08,51.61) v2(56.34,95.25) v2(56.34,75.41) v2(56.39,100.74) v2(56.39,69.95) v2(56.64,149.48) v2(56.64,146.94) v2(56.64,144.4) v2(56.64,141.86) v2(56.64,139.32) v2(56.64,136.78) v2(56.57,82.14) v2(56.64,31.37) v2(56.72,105.31) v2(56.82,99.14) v2(56.76,65.43) v2(56.77,0.64) v2(56.9,26.04) v2(57.02,87.88) v2(57.02,85.98) v2(56.97,71.63) v2(57.12,92.43) v2(57.33,104.72) v2(57.3,94.34) v2(57.3,76.38) v2(57.35,78.31) v2(57.36,66) v2(57.51,37.49) v2(57.78,131.7) v2(57.78,89.66) v2(57.78,48.34) v2(57.78,40.41) v2(57.91,126.62) v2(57.91,117.73) v2(57.91,115.19) v2(57.91,112.65) v2(57.91,110.11) v2(57.96,42.7) v2(58.01,30.1) v2(58.14,151.45) v2(58.17,83.95) v2(58.28,100.37) v2(58.3,70.32) v2(58.32,45.19) v2(58.42,59.61) v2(58.45,57.05) v2(58.39,27.05) v2(58.55,124.71) v2(58.55,122.17) v2(58.55,119.63) v2(58.5,105.54) v2(58.55,103.02) v2(58.5,98.17) v2(58.52,54.51) v2(58.57,72.57) v2(58.62,67.64) v2(58.65,65.18) v2(58.62,51.61) v2(58.72,80.04) v2(59,101.09) v2(59.03,87.88) v2(59.03,86) v2(59.02,69.6) v2(59.18,149.48) v2(59.18,146.94) v2(59.18,144.4) v2(59.18,141.86) v2(59.18,139.32) v2(59.18,136.78) v2(59.28,94.31) v2(59.33,92.38) v2(59.28,78.28) v2(59.31,0.64) v2(59.49,96.47) v2(59.51,76.4) v2(59.46,74.17) v2(59.92,82.3) v2(59.89,61.52) v2(60.33,89.66) v2(60.33,68.25) v2(60.3,37.54) v2(60.35,102.46) v2(60.43,40.34) v2(60.38,25.58) v2(60.45,134.24) v2(60.45,131.7) v2(60.45,129.16) v2(60.45,117.73) v2(60.45,115.19) v2(60.45,112.65) v2(60.45,110.11) v2(60.55,45.16) v2(60.55,42.62) v2(60.71,83.95) v2(60.71,9.26) v2(60.71,8.34) v2(60.81,6.73) v2(60.88,94.34) v2(60.93,92.38) v2(61.04,95.63) v2(60.96,59.61) v2(60.99,57.05) v2(61.09,126.62) v2(61.09,124.71) v2(61.09,122.17) v2(61.09,119.63) v2(61.14,100.86) v2(61.11,75.13) v2(61.06,54.51) v2(61.09,51.59) v2(61.24,69.88) v2(61.19,63.53) v2(61.21,47.98) v2(61.16,2.18) v2(61.32,78.31) v2(61.34,5.97) v2(61.44,151.45) v2(61.49,83.54) v2(61.47,76.4) v2(61.52,4.88) v2(61.52,3.76) v2(61.72,149.48) v2(61.72,146.94) v2(61.72,144.4) v2(61.72,141.86) v2(61.72,139.32) v2(61.72,136.78) v2(61.72,106.93) v2(61.85,0.64) v2(62.03,117.27) v2(62.03,115.57) v2(61.98,9.26) v2(61.98,8.34) v2(62.09,48.5) v2(62.09,46.75) v2(62.41,94.69) v2(62.41,82.6) v2(62.43,75.97) v2(62.41,4.85) v2(62.41,3.76) v2(62.46,102.59) v2(62.61,91.19) v2(62.76,116.41) v2(62.84,79.98) v2(62.84,45.47) v2(62.84,42.93) v2(62.84,37.54) v2(62.87,99.9) v2(62.87,70.76) v2(62.85,47.69) v2(62.89,34.57) v2(62.99,134.24) v2(62.99,131.7) v2(62.99,129.16) v2(62.99,112.65) v2(62.99,110.11) v2(62.97,40.34) v2(63.17,103.68) v2(63.25,65.46) v2(63.25,9.26) v2(63.25,8.34) v2(63.3,105.33) v2(63.3,67.06) v2(63.49,117.28) v2(63.5,115.53) v2(63.63,126.62) v2(63.63,124.71) v2(63.63,122.17) v2(63.63,119.63) v2(63.64,48.53) v2(63.64,46.75) v2(63.7,98.4) v2(63.73,72.34) v2(63.98,151.45) v2(64.01,59.72) v2(64.03,57.05) v2(64.14,103.07) v2(64.16,93.42) v2(64.16,82.14) v2(64.16,77.29) v2(64.16,54.46) v2(64.19,7.32) v2(64.24,4.93) v2(64.26,141.86) v2(64.26,139.32) v2(64.26,136.78) v2(64.31,67.77) v2(64.29,2.11) v2(64.39,13.84) v2(64.44,11.02) v2(64.39,0.64) v2(64.52,16.64) v2(64.64,96.95) v2(64.62,51.54) v2(64.67,73.71) v2(64.87,105.36) v2(64.92,65.43) v2(65.02,89.23) v2(65,86.92) v2(64.97,20.47) v2(65.07,102.11) v2(65.07,99.92) v2(65.07,98.55) v2(65.13,92.43) v2(65.07,72.64) v2(65.1,70.82) v2(65.1,68.53) v2(65.28,78.38) v2(65.41,134.11) v2(65.41,131.57) v2(65.53,146.94) v2(65.53,112.65) v2(65.53,110.11) v2(65.48,104.47) v2(65.63,66.4) v2(65.84,86.03) v2(65.94,95.2) v2(65.96,106.32) v2(65.96,75.46) v2(66.29,40.89) v2(66.27,31.67) v2(66.29,14.45) v2(66.27,9.17) v2(66.29,7.09) v2(66.45,84.48) v2(66.4,29.08) v2(66.42,27.13) v2(66.4,18.01) v2(66.4,12.5) v2(66.4,11.4) v2(66.5,126.67) v2(66.5,103.43) v2(66.47,67.23) v2(66.78,4.93) v2(66.83,2.11) v2(66.93,94.23) v2(66.93,57.23) v2(66.93,0.64) v2(67.03,151.45) v2(66.95,99.95) v2(66.95,98.5) v2(67.03,76.53) v2(66.98,72.59) v2(66.98,70.74) v2(67.01,69.22) v2(67.13,89.23) v2(67.13,87) v2(67.13,62.36) v2(67.06,54.64) v2(67.08,8.13) v2(67.16,59.11) v2(67.18,51.56) v2(67.18,12.5) v2(67.18,11.4) v2(67.26,120.73) v2(67.26,111.63) v2(67.51,20.47) v2(67.69,14.35) v2(67.92,82.25) v2(67.87,9.17) v2(67.89,7.09) v2(68.07,133.6) v2(68.17,96.29) v2(68.2,73.51) v2(68.2,13.61) v2(68.43,63.6) v2(68.58,99.03) v2(68.61,85.67) v2(68.71,131.7) v2(68.71,106.93) v2(68.81,76.38) v2(68.83,40.89) v2(68.81,31.67) v2(68.94,57.48) v2(68.95,48.53) v2(68.95,46.78) v2(68.94,29.08) v2(68.96,91.01) v2(68.96,27.13) v2(69.27,38.05) v2(69.37,80.11) v2(69.36,35.25) v2(69.39,33.72) v2(69.52,103.84) v2(69.52,101.3) v2(69.47,67.31) v2(69.47,0.64) v2(69.57,151.45) v2(69.71,47.72) v2(69.67,36.65) v2(69.98,146.3) v2(69.98,143.13) v2(69.98,139.95) v2(69.98,125.98) v2(70.03,61.85) v2(70.23,71.37) v2(70.21,65.33) v2(70.23,51.54) v2(70.16,35.26) v2(70.16,33.72) v2(70.5,48.55) v2(70.5,46.78) v2(70.61,137.41) v2(70.61,131.7) v2(71.25,134.87) v2(71.27,99.03) v2(71.53,40.89) v2(71.88,54.33) v2(72.01,67.31) v2(71.96,63.78) v2(72.01,0.64) v2(72.11,60.45) v2(72.21,103.84) v2(72.21,101.3) v2(72.52,133.6) v2(72.77,71.37) v2(72.87,151.45) v2(73.1,107.44) v2(73.05,51.46) v2(73.15,131.7) v2(73.81,99.03) v2(73.86,65.71) v2(73.99,68.4) v2(74.14,110.87) v2(74.12,40.97) v2(74.16,122.63) v2(74.17,121.73) v2(74.17,109.94) v2(74.42,139.32) v2(74.47,64.01) v2(74.52,61.67) v2(74.55,56.36) v2(74.55,0.64) v2(74.63,58.45) v2(74.75,103.84) v2(74.75,101.3) v2(74.9,71.32) v2(75.06,146.3) v2(75.06,136.78) v2(75.06,131.7) v2(75.06,126.62) v2(75.31,23.65) v2(75.31,18.26) v2(75.41,151.45) v2(75.41,107.54) v2(75.44,21.06) v2(75.36,15.44) v2(75.36,13.31) v2(75.41,10.64) v2(75.46,26.09) v2(75.59,51.46) v2(75.66,28.56) v2(75.76,48.5) v2(75.76,46.75) v2(76,34.47) v2(76.2,29.34) v2(76.33,134.24) v2(76.52,47.69) v2(76.66,40.97) v2(76.83,27.43) v2(77.04,68.43) v2(77.01,66.07) v2(76.99,63.96) v2(77.04,61.62) v2(76.99,56.41) v2(77.06,58.5) v2(77.09,0.64) v2(77.3,48.53) v2(77.3,46.75) v2(77.6,110.11) v2(77.6,107.57) v2(77.65,72.16) v2(78.31,51.49) v2(78.44,54.36) v2(78.38,34.44) v2(78.72,151.45) v2(78.87,106.3) v2(78.92,71.25) v2(79.08,41.36) v2(79.1,40.52) v2(79.35,63.93) v2(79.35,56.39) v2(79.38,68.43) v2(79.38,66.04) v2(79.4,61.59) v2(79.43,58.47) v2(79.5,136.78) v2(79.63,0.64) v2(80.14,134.24) v2(80.14,132.33) v2(80.14,127.25) v2(80.14,125.35) v2(80.24,144.78) v2(80.63,41.33) v2(80.64,40.52) v2(80.77,141.22) v2(80.77,114.55) v2(80.85,51.49) v2(80.92,34.44) v2(81.18,107.44) v2(81.23,104.57) v2(81.18,101.65) v2(81.26,151.45) v2(81.74,56.34) v2(81.67,40.43) v2(81.79,113.49) v2(81.84,111.12) v2(81.84,68.4) v2(81.81,58.42) v2(81.89,65.94) v2(81.86,63.83) v2(81.92,61.49) v2(82.19,38.46) v2(82.17,0.64) v2(82.27,35.99) v2(82.41,40.94) v2(83.3,48.53) v2(83.3,46.78) v2(83.39,51.49) v2(83.57,142.24) v2(83.57,139.7) v2(83.57,137.16) v2(83.57,134.62) v2(83.57,132.08) v2(83.67,41.02) v2(83.95,146.94) v2(84.06,47.72) v2(84.45,63.75) v2(84.51,61.42) v2(84.63,54.15) v2(84.71,0.64) v2(84.85,48.55) v2(84.85,46.78) v2(84.81,38.48) v2(85.06,41.55) v2(85.57,151.58) v2(85.85,141.22) v2(85.85,124.71) v2(85.85,122.17) v2(85.85,117.09) v2(85.85,105.66) v2(85.85,103.12) v2(85.98,66.93) v2(86.21,41.55) v2(86.49,51.51) v2(86.61,8.89) v2(86.64,6.48) v2(86.64,4.95) v2(86.64,3.43) v2(86.72,11.42) v2(86.73,10.5) v2(86.87,133.6) v2(86.87,131.06) v2(87.15,35.86) v2(87.2,144.96) v2(87.25,0.64) v2(87.38,65.41) v2(87.5,68.45) v2(87.48,61.59) v2(88.14,63.75) v2(88.29,12.04) v2(88.37,151.58) v2(88.39,146.94) v2(88.39,134.87) v2(88.39,132.33) v2(88.39,129.79) v2(88.39,127.25) v2(88.39,124.71) v2(88.39,122.17) v2(88.39,119.63) v2(88.49,7.67) v2(88.54,4.85) v2(88.54,2.72) v2(88.9,66.93) v2(88.93,44.32) v2(89.03,51.51) v2(89.15,22.76) v2(89.15,20.22) v2(89.15,14.83) v2(89.2,9.88) v2(89.28,17.63) v2(89.64,41.3) v2(89.66,141.22) v2(89.74,58.52) v2(89.71,56.41) v2(89.66,38.3) v2(89.69,35.86) v2(89.76,54.08) v2(89.79,0.64) v2(89.92,60.45) v2(90.17,136.14) v2(90.53,24.9) v2(90.55,63.75) v2(90.65,44.3) v2(90.91,151.58) v2(90.93,134.87) v2(90.93,132.33) v2(90.93,129.79) v2(90.93,127.25) v2(90.93,124.71) v2(90.93,122.17) v2(90.93,119.63) v2(90.86,12.06) v2(91.3,24.39) v2(91.44,62.36) v2(91.57,58.67) v2(91.74,51.54) v2(91.72,22.86) v2(91.72,20.32) v2(91.72,14.94) v2(91.69,2.64) v2(91.85,17.73) v2(91.77,9.98) v2(91.9,38.13) v2(92.02,55.4) v2(92.33,0.64) v2(92.94,7.95) v2(93.01,149.71) v2(92.96,60.71) v2(92.96,34.59) v2(93.33,22.26) v2(93.36,20.71) v2(93.47,147.57) v2(93.47,145.03) v2(93.47,142.49) v2(93.47,139.95) v2(93.47,137.41) v2(93.47,134.87) v2(93.47,132.33) v2(93.47,129.79) v2(93.47,127.25) v2(93.47,124.71) v2(93.47,122.17) v2(93.47,119.63) v2(93.47,107.57) v2(93.57,36.3) v2(93.87,6.27) v2(93.87,4.24) v2(93.98,56.36) v2(94.21,151.58) v2(94.23,14.5) v2(94.28,51.54) v2(94.26,2.74) v2(94.37,21.48) v2(94.63,5.2) v2(94.74,48.82) v2(94.84,38.13) v2(94.95,123.24) v2(94.87,0.64) v2(95.33,41.17) v2(95.39,22.26) v2(95.39,20.71) v2(95.42,6.24) v2(95.42,4.19) v2(95.48,58.17) v2(95.5,8.05) v2(95.63,149.78) v2(96.01,147.57) v2(96.01,145.03) v2(96.01,142.49) v2(96.01,139.95) v2(96.01,137.41) v2(96.01,134.87) v2(96.01,132.33) v2(96.01,129.79) v2(96.01,127.25) v2(96.01,124.71) v2(96.19,36.3) v2(96.65,21.67) v2(96.62,16.89) v2(96.67,53.72) v2(96.74,26.33) v2(96.74,24.3) v2(96.82,51.54) v2(96.77,19.08) v2(96.76,11.63) v2(96.76,9.6) v2(97.13,33.55) v2(97.13,31.01) v2(97.23,38.68) v2(97.26,28.42) v2(97.42,6.29) v2(97.42,4.26) v2(97.38,2.54) v2(97.41,0.64) v2(97.51,151.58) v2(97.52,9.15) v2(97.92,43.66) v2(97.85,24.6) v2(97.94,14.25) v2(98.04,55.6) v2(98.06,25.49) v2(98.06,8.38) v2(98.32,23.74) v2(98.3,22.86) v2(98.31,21.96) v2(98.29,13.09) v2(98.28,12.21) v2(98.28,11.31) v2(98.55,145.03) v2(98.55,142.49) v2(98.55,139.95) v2(98.55,137.41) v2(98.55,134.87) v2(98.55,132.33) v2(98.55,129.79) v2(98.55,127.25) v2(98.55,124.71) v2(98.91,31.75) v2(99.14,36.3) v2(99.31,33.15) v2(99.67,51.54) v2(99.67,48.72) v2(99.85,41.17) v2(99.9,38.63) v2(99.95,2.64) v2(99.95,0.64) v2(100.03,123.24) v2(100.05,151.58) v2(100.44,16.86) v2(100.86,43.66) v2(101.04,147.55) v2(101.09,145.03) v2(101.09,142.49) v2(101.09,139.95) v2(101.09,137.41) v2(101.09,134.87) v2(101.09,132.33) v2(101.09,129.79) v2(101.09,127.25) v2(101.09,124.71) v2(101.21,16.4) v2(101.47,122.17) v2(101.47,119.63) v2(102.41,51.61) v2(102.46,149.61) v2(102.49,0.64) v2(102.59,151.58) v2(102.62,48.72) v2(102.59,41.63) v2(103.63,147.57) v2(103.63,145.03) v2(103.63,142.49) v2(103.63,139.95) v2(103.63,137.41) v2(103.63,134.87) v2(103.63,132.33) v2(103.63,129.79) v2(103.63,127.25) v2(103.63,124.71) v2(103.63,122.17) v2(103.63,119.63) v2(103.94,40.28) v2(103.89,7.75) v2(103.89,5.21) v2(103.89,2.67) v2(104.64,13.09) v2(104.62,12.21) v2(104.63,11.31) v2(105.01,151.58) v2(105,149.61) v2(105.03,0.64) v2(105.13,51.64) v2(105.16,3.96) v2(105.28,34.85) v2(105.28,32.31) v2(105.28,29.77) v2(105.28,27.23) v2(105.28,24.69) v2(105.38,37.41) v2(105.54,43.64) v2(105.71,9.45) v2(105.71,6.91) v2(105.77,49.4) v2(106.17,147.57) v2(106.17,145.03) v2(106.17,142.49) v2(106.17,139.95) v2(106.17,137.41) v2(106.17,134.87) v2(106.17,132.33) v2(106.17,129.79) v2(106.17,127.25) v2(106.17,124.71) v2(106.17,122.17) v2(106.17,119.63) v2(107.19,151.64) v2(107.19,23.75) v2(107.17,22.87) v2(107.18,21.98) v2(107.2,13.07) v2(107.18,12.19) v2(107.19,11.29) v2(107.44,149.58) v2(107.52,49.43) v2(107.57,0.64) v2(107.67,51.64) v2(108.17,36.95) v2(108.17,35.68) v2(108.23,34.85) v2(108.23,32.31) v2(108.23,29.77) v2(108.23,27.23) v2(108.23,24.69) v2(108.23,22.15) v2(108.23,19.61) v2(108.23,17.07) v2(108.23,14.53) v2(108.23,11.99) v2(108.23,9.45) v2(108.23,6.91) v2(108.71,145.03) v2(108.71,142.49) v2(108.71,139.95) v2(108.71,137.41) v2(108.71,134.87) v2(108.71,132.33) v2(108.71,129.79) v2(108.71,127.25) v2(108.71,124.71) v2(108.71,122.17) v2(108.71,119.63) v2(108.76,147.5) v2(109.73,151.64) v2(110.11,0.64) v2(110.21,51.64) v2(110.77,34.85) v2(110.77,32.31) v2(110.77,29.77) v2(110.77,27.23) v2(110.77,24.69) v2(110.77,22.15) v2(110.77,19.61) v2(110.77,17.07) v2(110.77,14.53) v2(110.77,11.99) v2(110.77,9.45) v2(110.77,6.91) v2(111.51,151.64) v2(111.51,149.1) v2(111.51,145.29) v2(111.51,142.75) v2(111.51,140.08) v2(111.51,137.54) v2(111.51,134.62) v2(111.51,132.08) v2(111.51,129.29) v2(111.51,126.75) v2(111.51,123.83) v2(111.51,121.28) v2(111.51,118.75) v2(111.51,116.2) v2(111.63,47.37) v2(111.63,44.58) v2(111.63,41.66) v2(111.63,38.48) v2(111.63,34.16) v2(111.63,31.62) v2(111.63,28.45) v2(111.63,26.16) v2(111.63,23.62) v2(111.63,21.59) v2(111.63,18.8) v2(111.63,16.26) v2(111.63,13.46) v2(111.63,10.92) v2(111.63,8.51) v2(111.63,5.97) v2(111.63,3.56) v2(111.63,1.02) v2(111.68,49.38) v2(112.65,114.68) v2(113.31,51.66) v2(113.54,47.62) v2(114.22,49.38) v2(115.19,114.68) v2(115.85,51.66) v2(116.59,47.62) v2(116.76,49.38) v2(117.73,114.68) v2(118.57,51.69) v2(119.25,47.62) v2(119.86,49.4) v2(120.27,114.68) v2(121.11,51.69) v2(121.79,47.62) v2(122.4,49.4) v2(123.47,111.99) v2(123.57,114.68) v2(123.65,51.69) v2(124.21,47.62) v2(125.12,49.43) v2(126.01,111.99) v2(126.11,114.68) v2(126.09,51.71) v2(126.75,47.62) v2(127.66,49.43) v2(128.55,111.99) v2(129.03,47.62) v2(129.29,114.68) v2(130.2,49.43) v2(131.09,111.99) v2(131.42,107.57) v2(131.57,47.62) v2(131.72,53.87) v2(131.72,51.33) v2(131.83,114.68) v2(132.82,110.9) v2(134.65,107.42) v2(134.67,108.92) v2(135.97,56.01) v2(136.96,54.99) v2(137.29,47.62) v2(137.67,114.68) v2(137.9,52.22) v2(138.71,111.51) v2(138.71,108.97) v2(139.83,47.62) v2(139.9,107.42) v2(140.21,114.68) v2(140.56,54.97) v2(140.56,49.89) v2(141.25,111.51) v2(141.25,108.97) v2(141.5,52.2) v2(142.62,107.47) v2(142.7,54.2) v2(142.75,47.62) v2(143,114.68) v2(143.79,111.51) v2(143.79,108.97) v2(145.11,110.03) v2(145.11,107.49) v2(145.11,104.95) v2(145.11,102.41) v2(145.11,99.87) v2(145.11,97.33) v2(145.11,94.79) v2(145.11,92.25) v2(145.11,89.71) v2(145.11,87.17) v2(145.11,84.63) v2(145.11,82.09) v2(145.11,79.6) v2(145.11,77.06) v2(145.11,74.52) v2(145.11,71.98) v2(145.11,69.44) v2(145.11,66.9) v2(145.11,64.36) v2(145.11,61.82) v2(145.11,59.28) v2(145.11,56.74) v2(145.11,54.2) v2(145.11,51.66) v2(145.16,49.35) v2(145.29,47.62) v2(145.54,114.68) v2(145.9,112.67) v2(147.65,110.03) v2(147.65,107.49) v2(147.65,104.95) v2(147.65,102.41) v2(147.65,99.87) v2(147.65,97.33) v2(147.65,94.79) v2(147.65,92.25) v2(147.65,89.71) v2(147.65,87.17) v2(147.65,84.63) v2(147.65,82.09) v2(147.65,79.6) v2(147.65,77.06) v2(147.65,74.52) v2(147.65,71.98) v2(147.65,69.44) v2(147.65,66.9) v2(147.65,64.36) v2(147.65,61.82) v2(147.65,59.28) v2(147.65,56.74) v2(147.65,54.2) v2(147.65,51.66) v2(147.7,49.35) v2(148.44,112.67) v2(149.1,114.68) v2(149.22,111.38) v2(149.22,108.33) v2(149.22,104.65) v2(149.22,102.11) v2(149.22,98.42) v2(149.22,95.89) v2(149.22,92.84) v2(149.22,90.3) v2(149.22,86.87) v2(149.22,83.44) v2(149.22,80.26) v2(149.22,77.09) v2(149.22,73.91) v2(149.22,71.12) v2(149.22,68.33) v2(149.22,65.41) v2(149.22,62.74) v2(149.22,60.2) v2(149.22,57.02) v2(149.22,53.21) v2(149.22,50.29) v2(149.22,47.75) v3(11.46,105.87) v3(11.46,104.88) v3(11.46,103.89) v3(11.46,102.9) v3(11.46,101.9) v3(12.45,105.87) v3(12.45,104.88) v3(12.45,103.89) v3(12.45,102.9) v3(12.45,101.9) v3(13.44,105.87) v3(13.44,104.88) v3(13.44,103.89) v3(13.44,102.9) v3(13.44,101.9) v3(14.43,105.87) v3(14.43,104.88) v3(14.43,103.89) v3(14.43,102.9) v3(15.42,105.87) v3(15.42,104.88) v3(15.42,103.89) v3(15.42,101.9) v4(16.1,106.65) v4(16.18,107.65) v4(16.18,107.14) v4(18.03,131.29) v4(18.03,127.79) v4(18.03,126.29) v4(18.94,131.29) v4(18.94,130.79) v4(18.94,127.79) v4(18.94,126.29) v4(19.74,131.29) v4(19.74,130.78) v4(19.74,127.79) v4(19.74,126.29) v4(22.01,41.8) v4(22.19,46.85) v4(22.17,46.34) v4(22.28,43.84) v4(22.75,48.84) v4(22.69,46.34) v4(22.82,47.84) v4(22.82,43.84) v4(22.82,41.84) v4(22.85,46.85) v4(23.27,137.01) v4(23.27,136.12) v4(23.27,135.31) v4(23.51,47.84) v4(23.52,46.84) v4(23.49,43.85) v4(23.63,48.84) v4(23.77,137.08) v4(23.77,136.32) v4(23.77,135.51) v4(24.79,136.14) v4(24.79,135.48) v4(24.79,122.78) v4(24.79,122) v4(25.78,136.22) v4(25.78,135.48) v4(26.29,122.17) v4(26.29,121.67) v4(26.77,136.12) v4(27.28,122.73) v4(27.28,121.74) v4(27.28,121.03) v4(28.69,51.45) v4(28.69,50.91) v4(28.69,50.39) v4(28.78,122.2) v4(28.78,121.64) v4(29.29,137.06) v4(29.29,136.04) v4(29.79,137.03) v4(29.79,136.25) v4(29.79,135.36) v4(31.19,40.8) v4(31.19,39.97) v4(31.19,39.15) v4(32.28,132.28) v4(32.26,131.29) v4(32.28,129.29) v4(32.33,127.28) v4(32.44,129.77) v4(32.51,132.79) v4(32.56,131.78) v4(33.19,132.78) v4(33.19,132.28) v4(33.25,131.78) v4(33.22,129.79) v4(33.24,127.28) v4(33.19,125.78) v4(33.25,48.34) v4(33.25,42.34) v4(33.48,131.29) v4(33.5,129.29) v4(33.91,132.79) v4(33.99,132.28) v4(34.04,127.28) v4(34.09,131.78) v4(34.11,129.79) v4(34.07,48.34) v4(34.07,42.34) v4(34.9,48.34) v4(34.9,42.34) v4(50.3,69.35) v4(50.38,101.42) v4(50.83,101.88) v4(50.77,68.9) v4(51.22,68.44) v4(51.29,102.33) v4(51.82,70.86) v4(51.88,99.92) v4(52.34,100.38) v4(52.28,70.4) v4(52.73,69.94) v4(52.79,100.83) v4(56.93,108.17) v4(57.04,62.44) v4(57.39,108.63) v4(57.5,61.98) v4(57.85,109.08) v4(57.95,61.52) v4(58.44,106.66) v4(58.55,63.94) v4(58.89,107.12) v4(59.01,63.48) v4(59.35,107.57) v4(59.46,63.03) v4(97.99,79.86) v4(98.12,91.03) v4(98.7,96.24) v4(99.36,79.86) v4(99.36,77.11) v4(100.3,94.82) v4(100.41,96.82) v4(100.76,79.86) v4(100.91,72.19) v4(101.24,96.04) v4(101.3,93.83) v4(102.69,80.82) v4(103.07,72.19) v4(103.33,96.06) v4(103.33,69.16) v4(103.43,79.86) v4(103.63,89.89) v4(103.66,93.55) v4(103.84,91.29) v4(103.78,78.31) v4(104.78,94.79) v4(104.78,76.02) v4(104.9,73.84) v4(105.23,72.19) v4(105.46,79.88) v4(105.49,69.16) v4(105.82,94.11) v4(105.82,76.94) v4(105.87,87.48) v4(105.87,78.18) v4(106.05,81.74) v4(106.07,85.19) v4(106.88,94.69) v4(106.93,76) v4(107.09,73.84) v4(107.19,84.61) v4(107.39,72.19) v4(107.65,69.16) v4(107.9,92.33) v4(108,94.11) v4(108,76.96) v4(108.05,78.21) v4(109.09,94.72) v4(109.14,76) v4(109.25,73.81) v4(109.32,84.94) v4(109.52,72.19) v4(109.8,83.08) v4(109.8,69.16) v4(109.86,81.51) v4(110.13,94.06) v4(110.11,76.96) v4(110.26,78.21) v4(111.25,94.59) v4(111.28,76) v4(111.4,73.84) v4(111.66,72.16) v4(111.91,83.13) v4(111.96,69.16) v4(112.24,76.96) v4(113.03,78.21) v4(113.18,79.91) v4(113.41,75.97) v4(113.56,73.84) v4(114,88.87) v4(114.07,97.94) v4(114.15,69.09) v4(114.53,93.47) v4(114.96,72.09) v4(115.19,91.11) v4(115.19,67.79) v4(115.72,79.25) v4(116.13,72.21) v4(116.61,74.85) v4(116.79,94.72) v4(117.37,69.19) v4(117.75,73.84) v4(117.98,100.51) v4(118.26,93.47) v4(118.29,72.21) v4(118.75,74.85) v4(118.77,76.94) v4(119.53,89.97) v4(119.48,80.26) v4(119.53,69.22) v4(119.89,91.26) v4(120.02,73.84) v4(120.42,72.24) v4(120.5,92.41) v4(120.55,66.75) v4(120.85,76.99) v4(120.93,74.83) v4(121.16,99.87) v4(121.31,79.27) v4(121.69,67.84) v4(121.87,81.56) v4(121.97,83.29) v4(122.15,97.82) v4(122.12,93.45) v4(122.12,73.84) v4(122.3,92.41) v4(122.3,80.29) v4(122.58,72.24) v4(122.76,69.11) v4(122.81,66.75) v4(122.91,70.38) v4(123.04,76.99) v4(123.06,74.85) v4(123.34,79.25) v4(123.85,85.14) v4(123.88,67.82) v4(124.23,73.84) v4(124.46,80.26) v4(124.84,84.58) v4(124.76,72.21) v4(124.87,89.81) v4(124.97,66.75) v4(125.07,70.36) v4(125.17,77.01) v4(125.25,74.85) v4(125.3,83.24) v4(126.03,69.22) v4(125.98,67.87) v4(126.14,97.76) v4(126.19,65.48) v4(127.3,66.93) v4(127.41,76.99) v4(128.32,73.43) v4(128.37,75.08) v4(128.42,71.93) v4(129.29,71.27) v4(129.41,64.21) v5(22.23,132.84) v5(22.23,131.57) v5(22.23,130.3) v5(22.23,129.03) v5(22.23,127.76) v5(22.23,126.49) v5(22.23,125.22) v5(23.5,132.84) v5(23.5,131.57) v5(23.5,130.3) v5(23.5,129.03) v5(23.5,127.76) v5(23.5,126.49) v5(23.5,125.22) v5(24.77,132.84) v5(24.77,131.57) v5(24.77,130.3) v5(24.77,129.03) v5(24.77,127.76) v5(24.77,126.49) v5(24.77,125.22) v5(26.04,132.84) v5(26.04,131.57) v5(26.04,130.3) v5(26.04,129.03) v5(26.04,127.76) v5(26.04,126.49) v5(26.04,125.22) v5(27.3,132.84) v5(27.3,131.57) v5(27.3,130.3) v5(27.3,129.03) v5(27.3,127.76) v5(27.3,126.49) v5(27.3,125.22) v5(28.57,132.84) v5(28.57,131.57) v5(28.57,130.3) v5(28.57,129.03) v5(28.57,127.76) v5(28.57,126.49) v5(28.57,125.22) v5(29.84,132.84) v5(29.84,131.57) v5(29.84,130.3) v5(29.84,129.03) v5(29.84,127.76) v5(29.84,126.49) v5(29.84,125.22) v5(94.69,116.74) v5(94.69,115.47) v5(94.69,114.2) v5(94.69,112.93) v5(94.69,111.66) v5(95.96,116.74) v5(95.96,115.47) v5(95.96,114.2) v5(95.96,112.93) v5(95.96,111.66) v5(97.23,116.74) v5(97.23,115.47) v5(97.23,114.2) v5(97.23,112.93) v5(97.23,111.66) v5(98.5,116.74) v5(98.5,115.47) v5(98.5,114.2) v5(98.5,112.93) v5(98.5,111.66) v5(99.77,116.74) v5(99.77,115.47) v5(99.77,114.2) v5(99.77,112.93) v5(99.77,111.66) v6(2.54,71.89) v6(2.54,70.79) v6(2.54,69.68) v6(2.54,68.58) v6(3.64,71.89) v6(3.64,70.79) v6(3.64,69.68) v6(3.64,68.58) v6(4.75,71.89) v6(4.75,70.79) v6(4.75,69.68) v6(4.75,68.58) v6(5.85,71.89) v6(5.85,70.79) v6(5.85,69.68) v6(5.85,68.58) v6(6.96,71.89) v6(6.96,70.79) v6(6.96,69.68) v6(6.96,68.58) v6(8.06,71.89) v6(8.06,70.79) v6(8.06,69.68) v6(8.06,68.58) v6(42.8,10.68) v6(42.8,9.58) v6(42.8,8.47) v6(42.8,7.37) v6(43.9,10.68) v6(43.9,9.58) v6(43.9,8.47) v6(43.9,7.37) v6(45.01,10.68) v6(45.01,9.58) v6(45.01,8.47) v6(45.01,7.37) v6(46.11,10.68) v6(46.11,9.58) v6(46.11,8.47) v6(46.11,7.37) v6(47.22,10.68) v6(47.22,9.58) v6(47.22,8.47) v6(47.22,7.37) v6(48.32,10.68) v6(48.32,9.58) v6(48.32,8.47) v6(48.32,7.37) v6(53.72,17.14) v6(53.72,15.88) v6(53.72,14.61) v6(54.99,17.14) v6(54.99,15.88) v6(54.99,14.61) v6(56.26,17.14) v6(56.26,15.88) v6(56.26,14.61) v6(57.53,17.14) v6(57.53,15.88) v6(57.53,14.61) v6(58.8,17.14) v6(58.8,15.88) v6(58.8,14.61) v6(60.07,17.14) v6(60.07,15.88) v6(60.07,14.61) v6(61.34,17.14) v6(61.34,15.88) v6(61.34,14.61) v6(68.83,117.94) v6(68.83,116.84) v6(68.83,115.74) v6(68.83,114.63) v6(69.94,117.94) v6(69.94,116.84) v6(69.94,115.74) v6(69.94,114.63) v6(71.04,117.94) v6(71.04,116.84) v6(71.04,115.74) v6(71.04,114.63) v6(72.15,117.94) v6(72.15,116.84) v6(72.15,115.74) v6(72.15,114.63) v6(73.25,117.94) v6(73.25,116.84) v6(73.25,115.74) v6(73.25,114.63) v6(74.36,117.94) v6(74.36,116.84) v6(74.36,115.74) v6(74.36,114.63) v6(78.45,20.79) v6(78.45,19.52) v6(78.45,18.25) v6(78.45,16.98) v6(78.45,15.68) v6(79.74,20.79) v6(79.74,19.52) v6(79.74,18.25) v6(79.74,16.98) v6(79.74,15.68) v6(81.01,20.79) v6(81.01,19.52) v6(81.01,18.25) v6(81.01,16.98) v6(81.01,15.68) v6(82.28,20.79) v6(82.28,19.52) v6(82.28,18.25) v6(82.28,16.98) v6(82.28,15.68) v6(83.55,20.79) v6(83.55,19.52) v6(83.55,18.25) v6(83.55,16.98) v6(83.55,15.68) v6(84.82,20.79) v6(84.82,19.52) v6(84.82,18.25) v6(84.82,16.98) v6(84.82,15.68) v6(86.09,20.79) v6(86.09,19.52) v6(86.09,18.25) v6(86.09,16.98) v6(86.09,15.68)
